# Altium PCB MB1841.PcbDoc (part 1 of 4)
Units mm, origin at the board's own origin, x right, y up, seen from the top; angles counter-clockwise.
Board outline 70 x 82.5 mm, 4 copper layers (Top Layer, Signal Layer 1, Signal Layer 2, Bottom Layer), stack 1.49 mm thick; 252 components, 169 nets, 1058 pads, 796 vias.
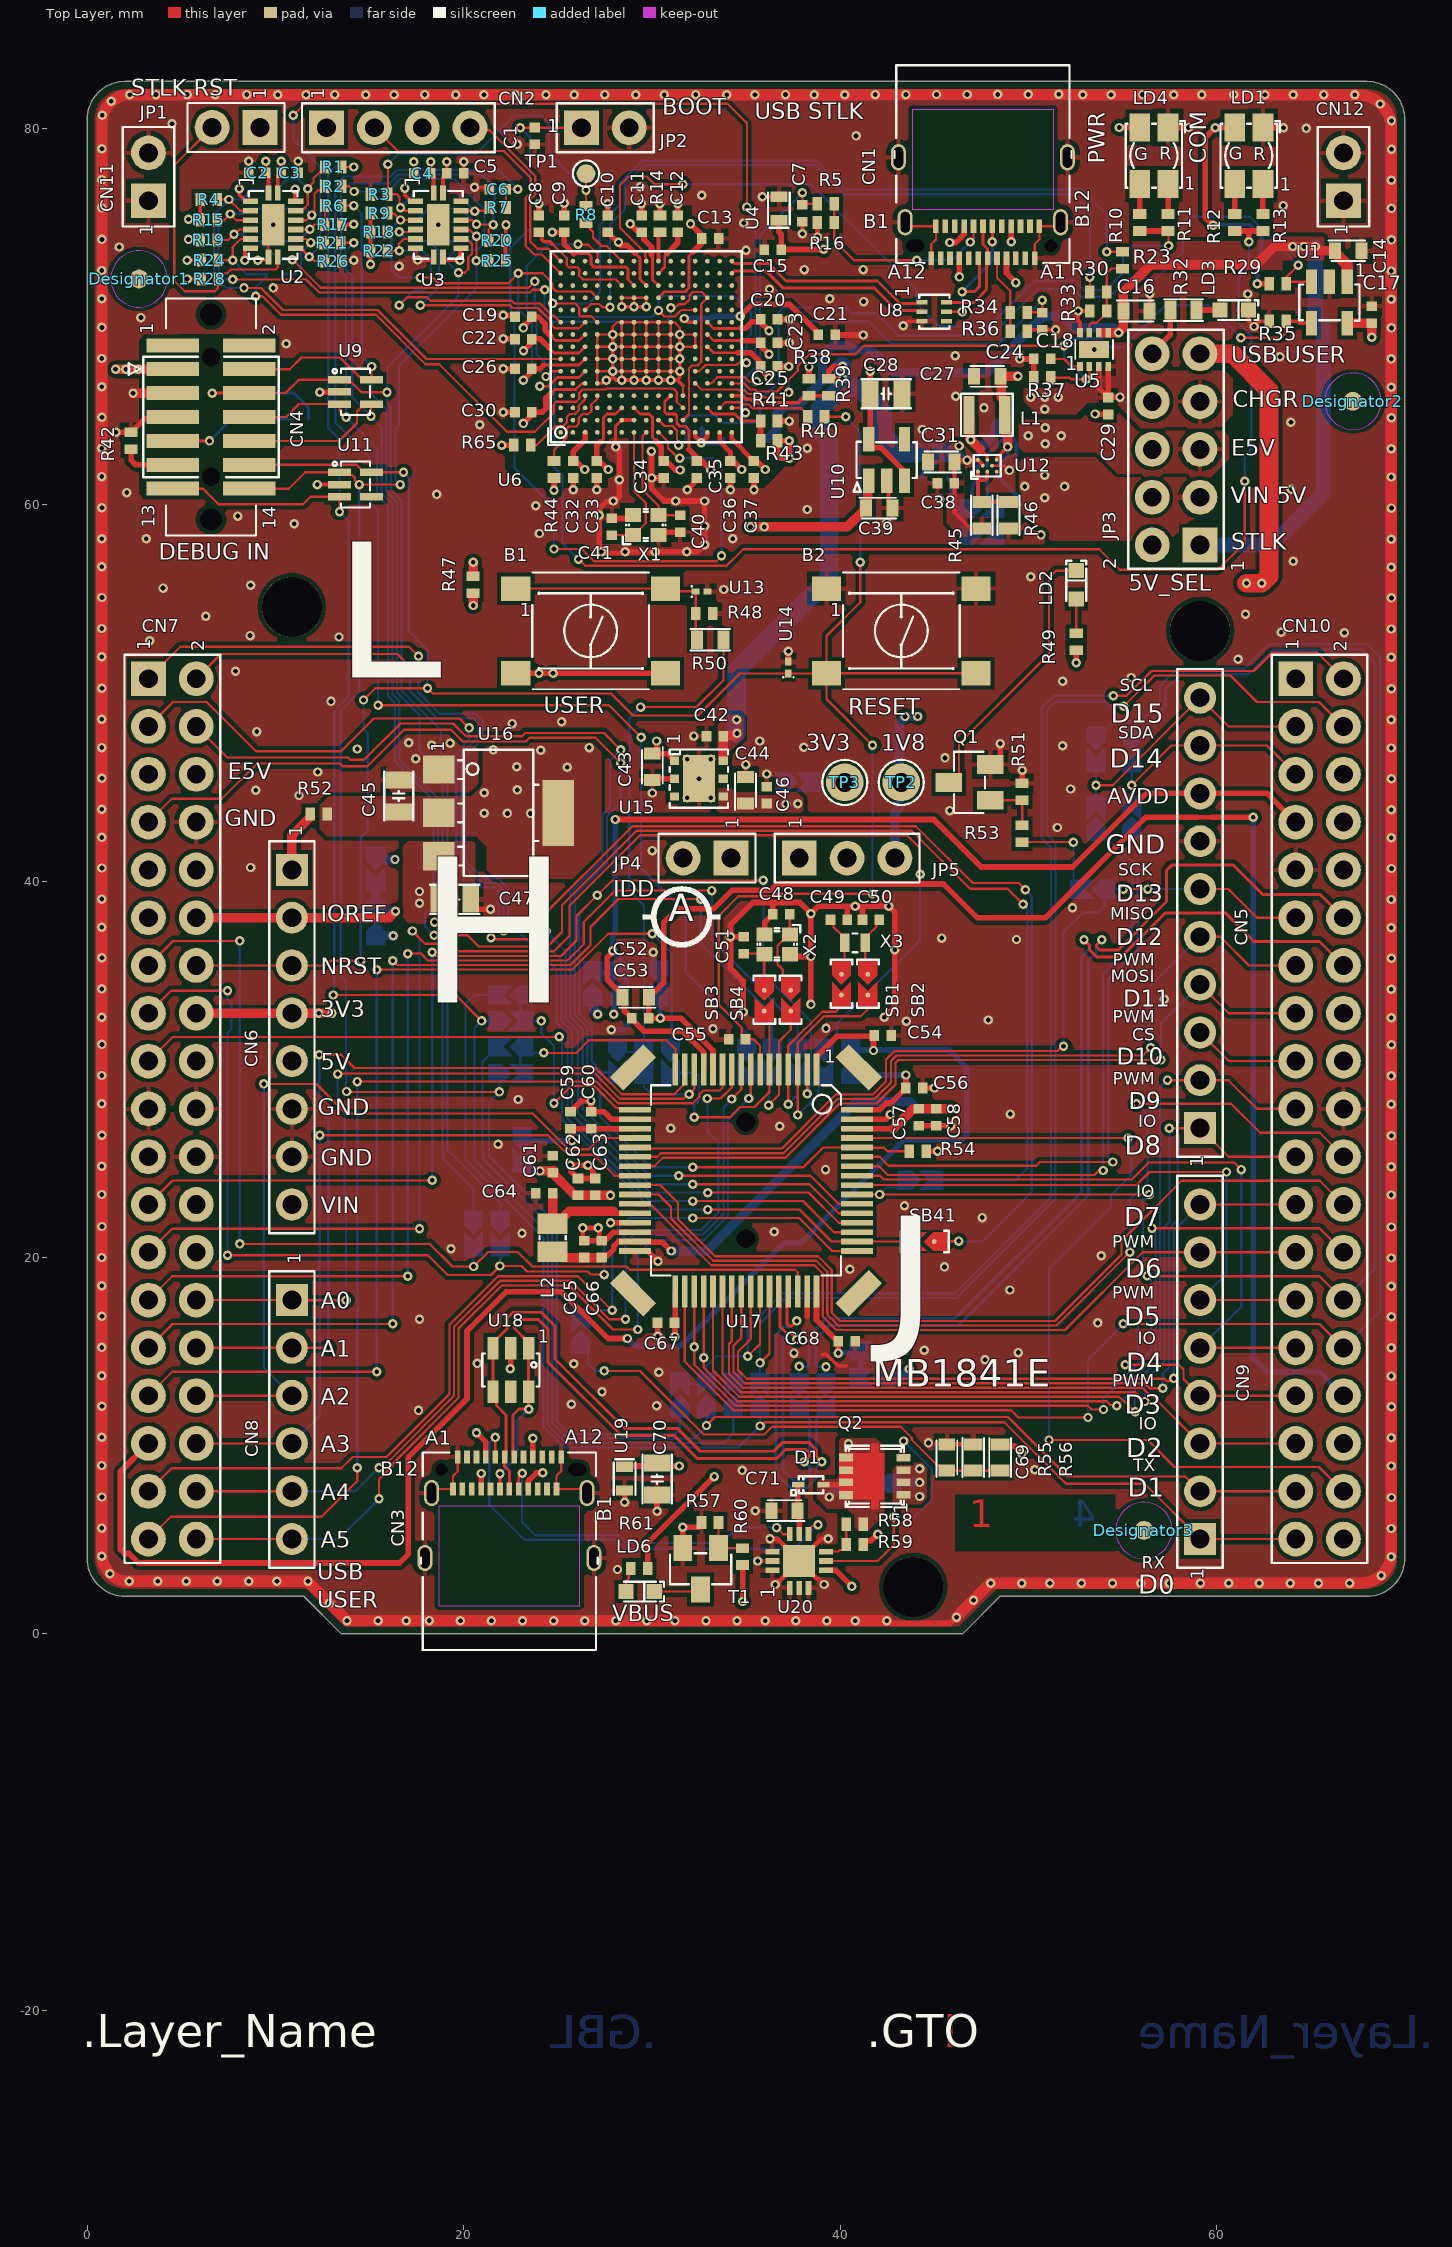
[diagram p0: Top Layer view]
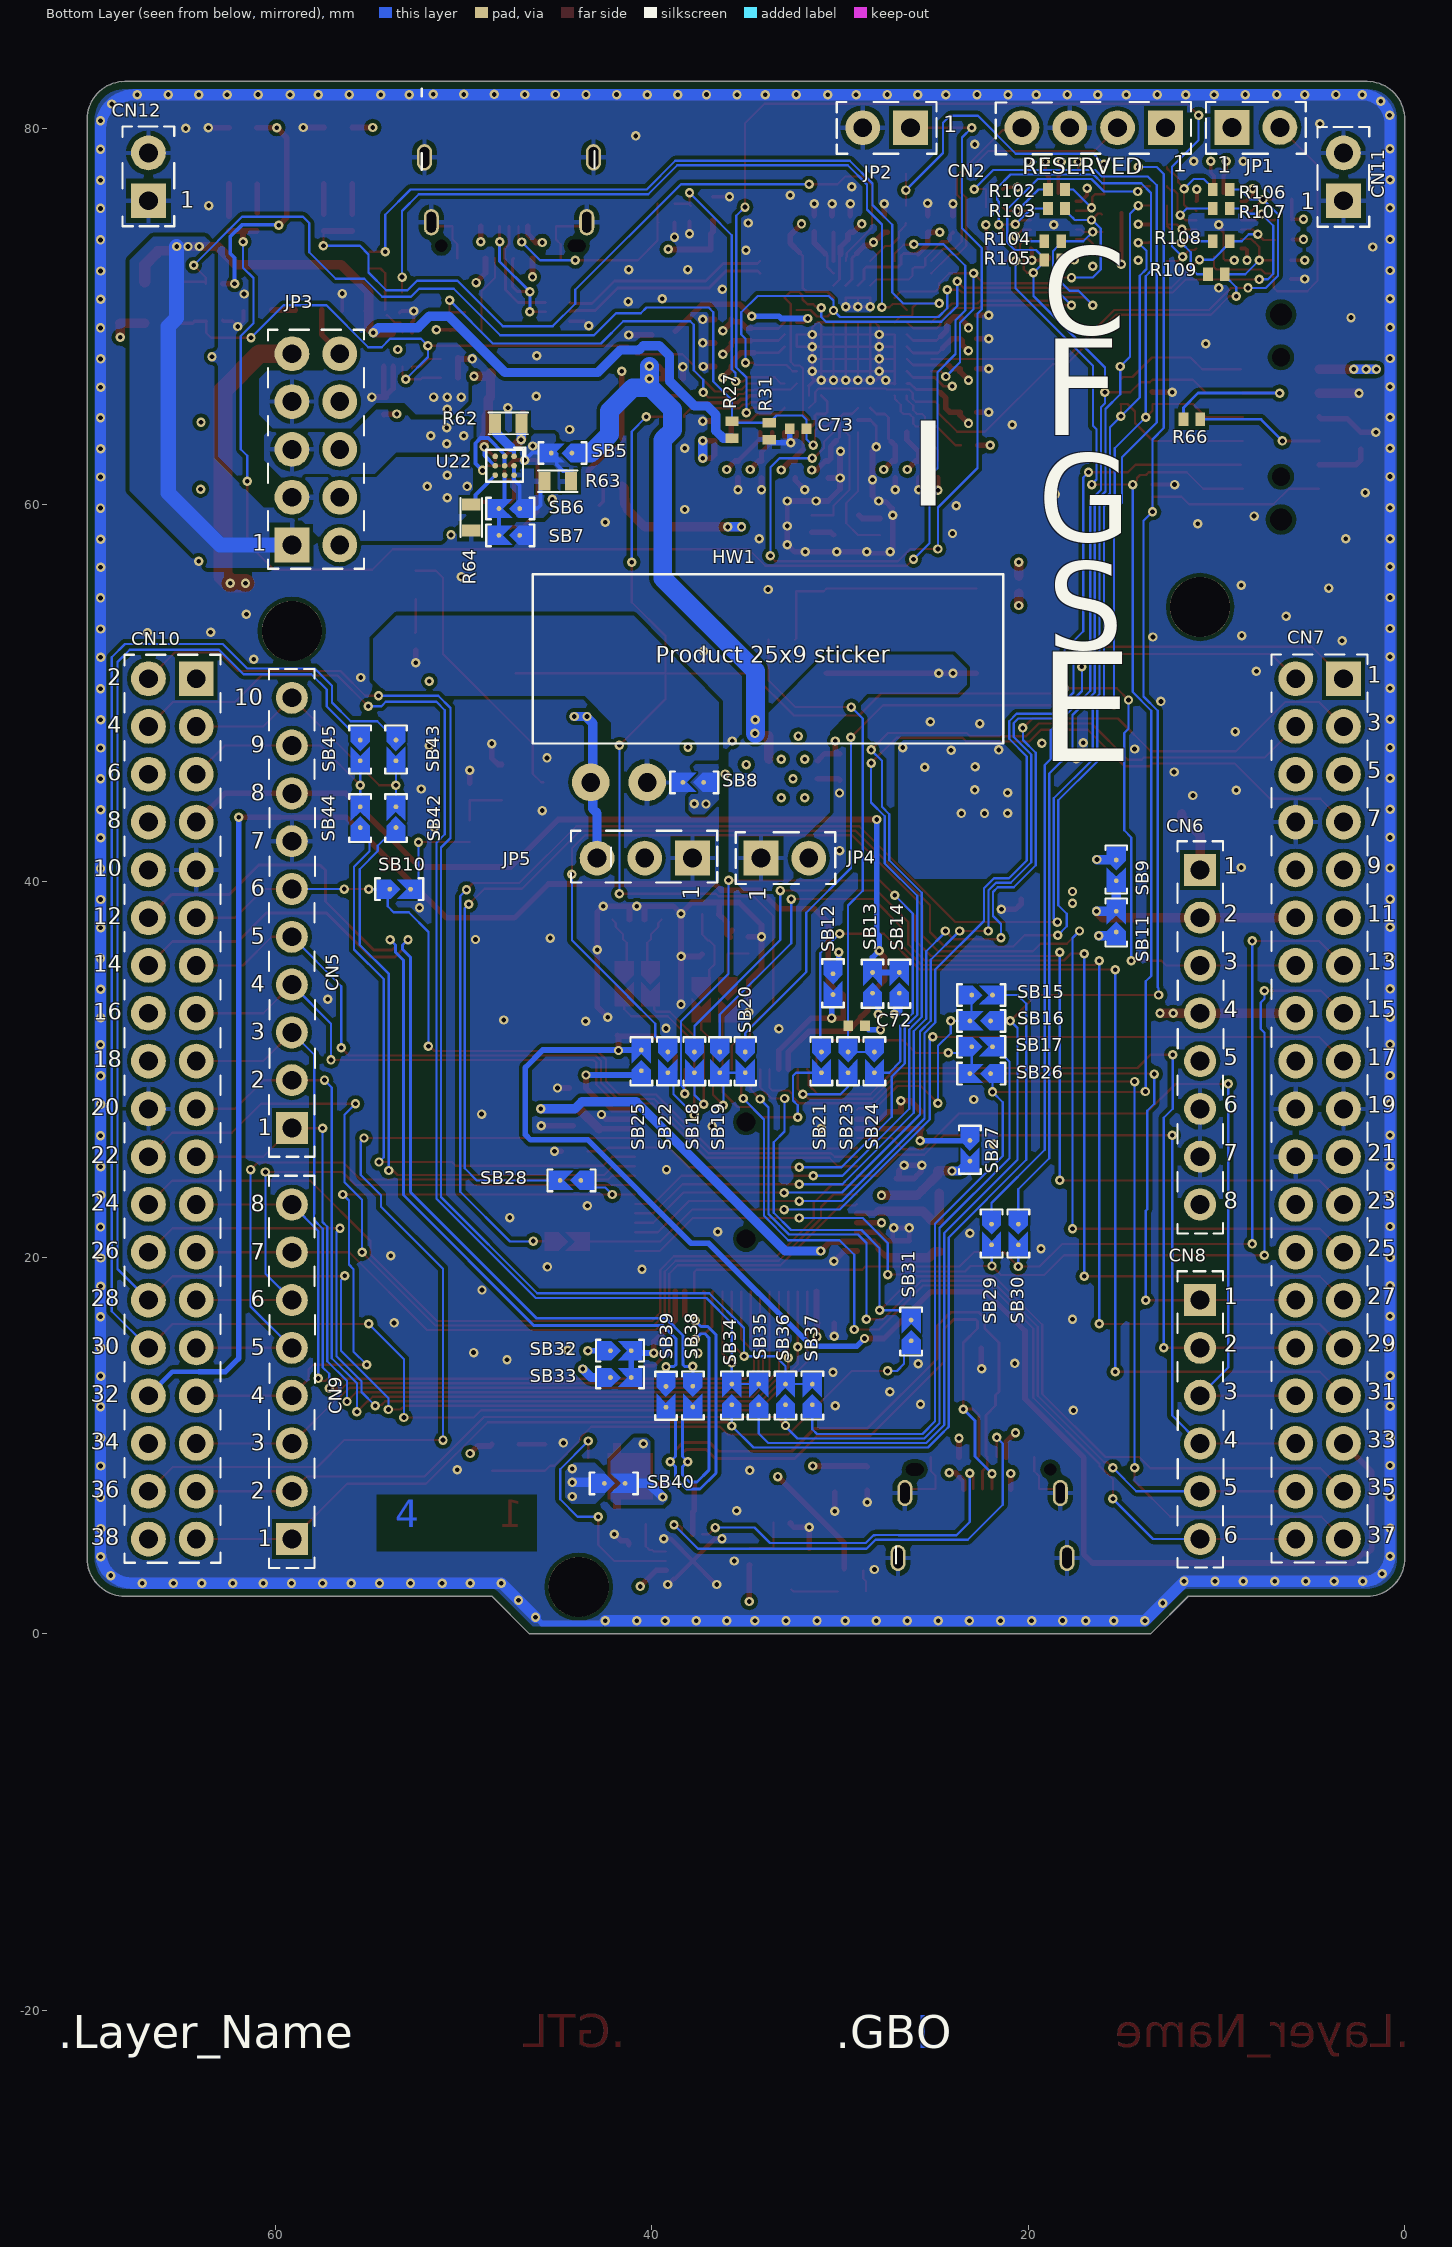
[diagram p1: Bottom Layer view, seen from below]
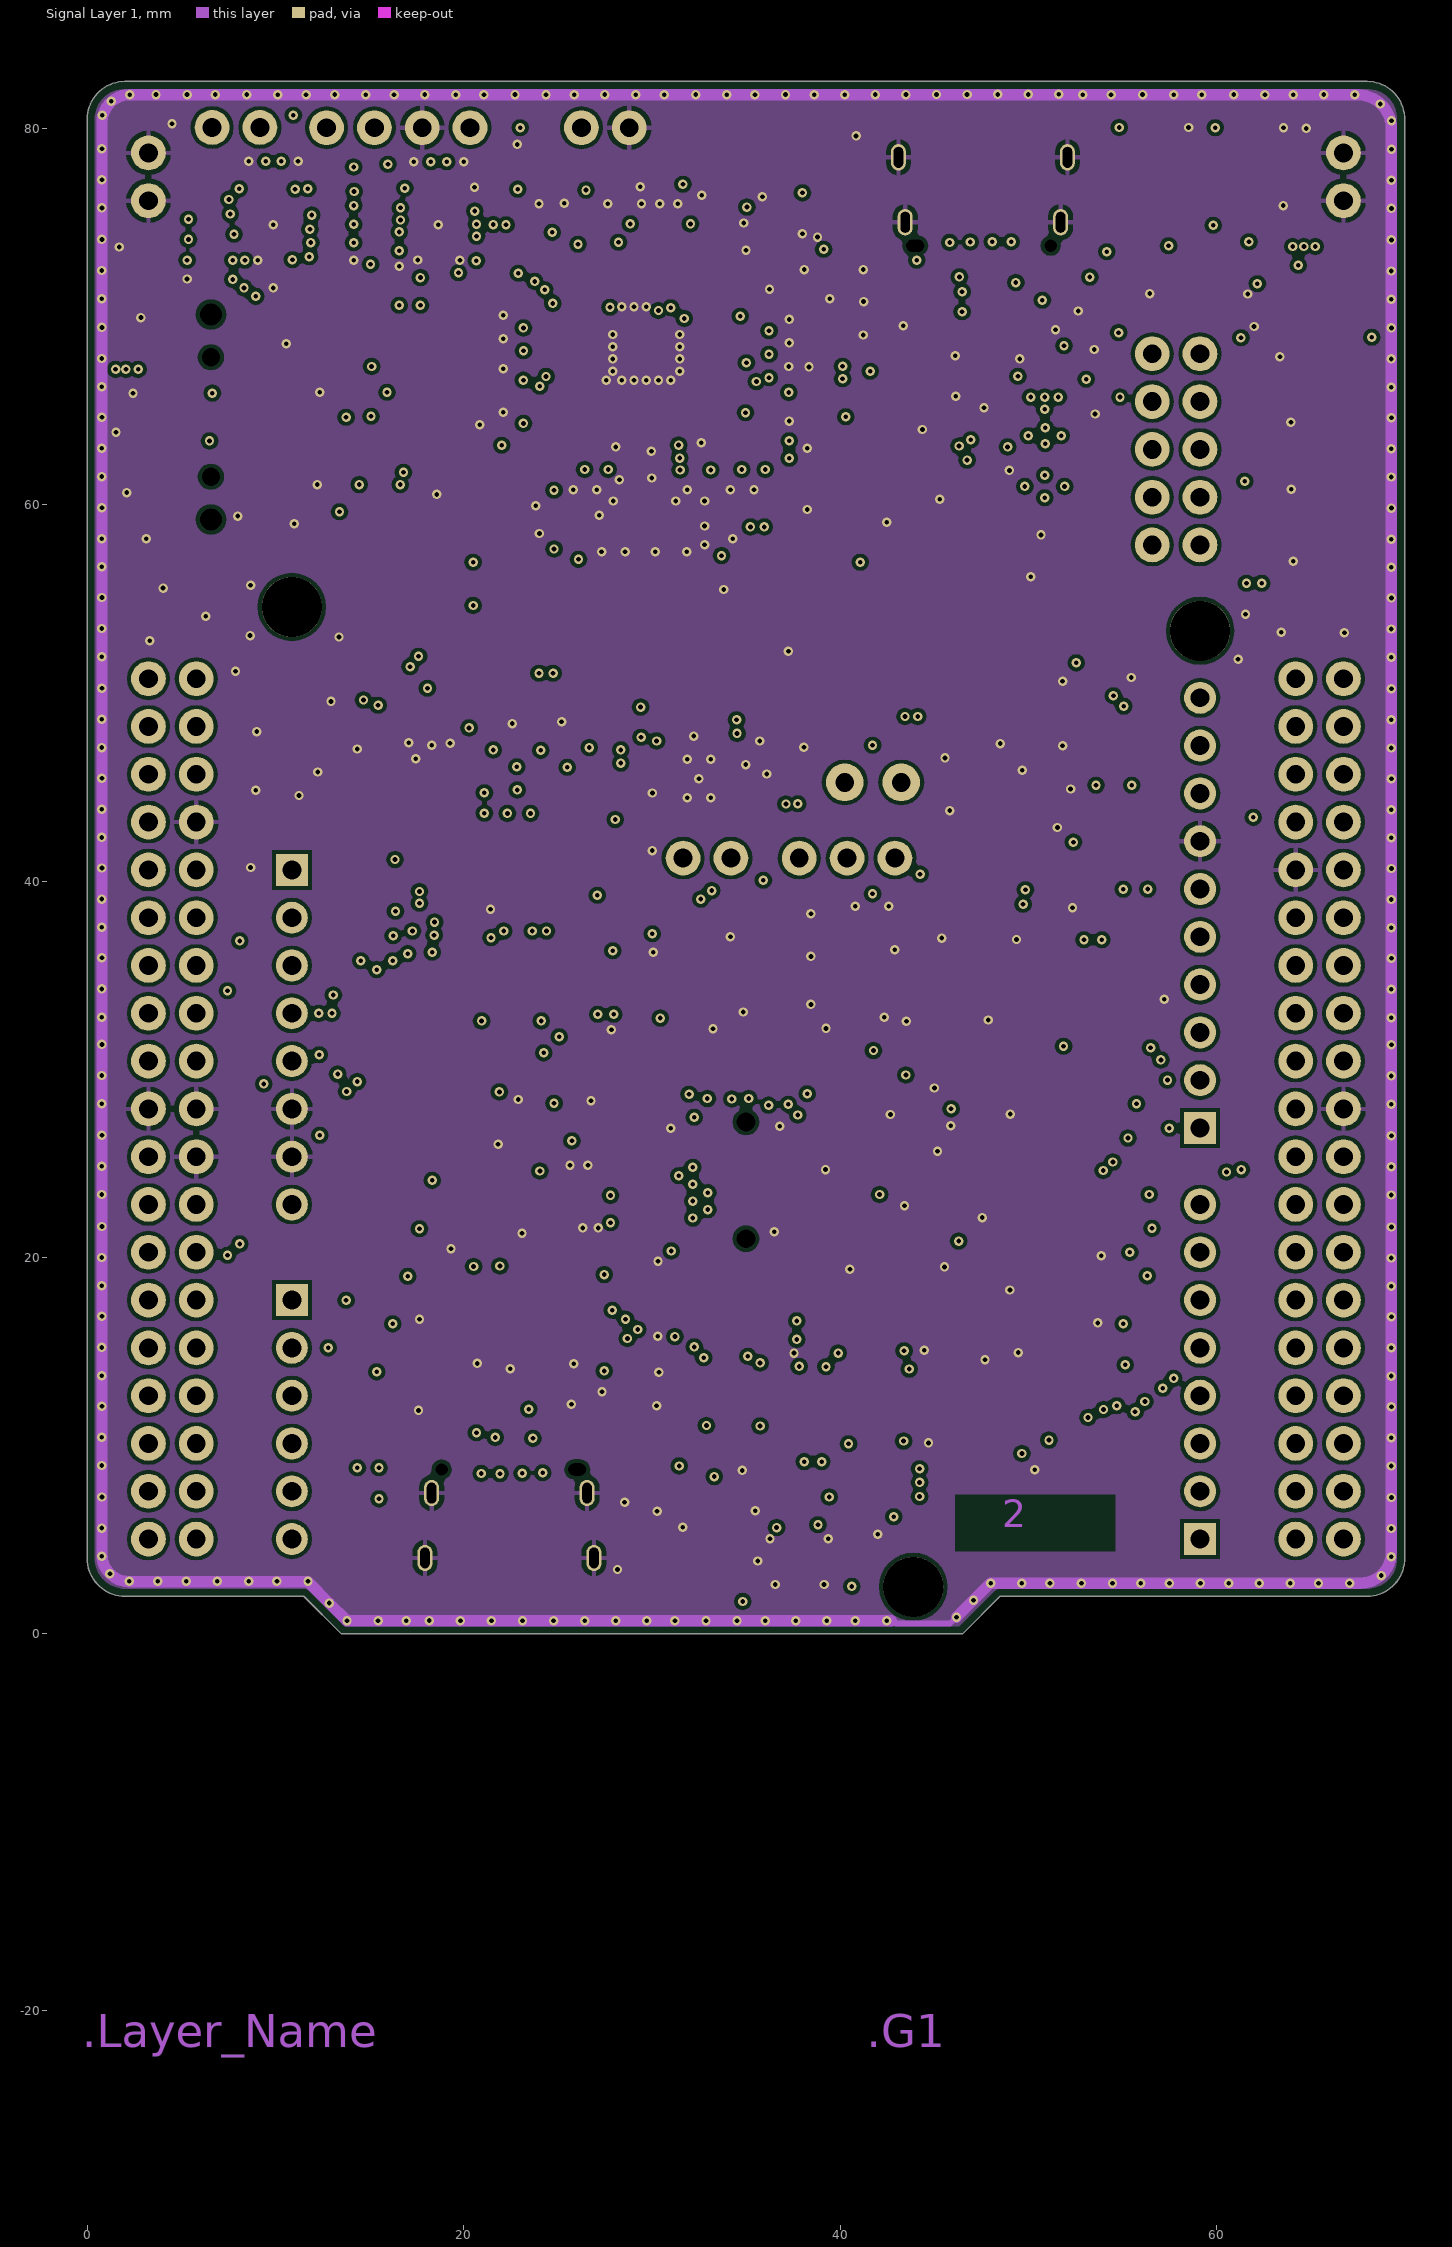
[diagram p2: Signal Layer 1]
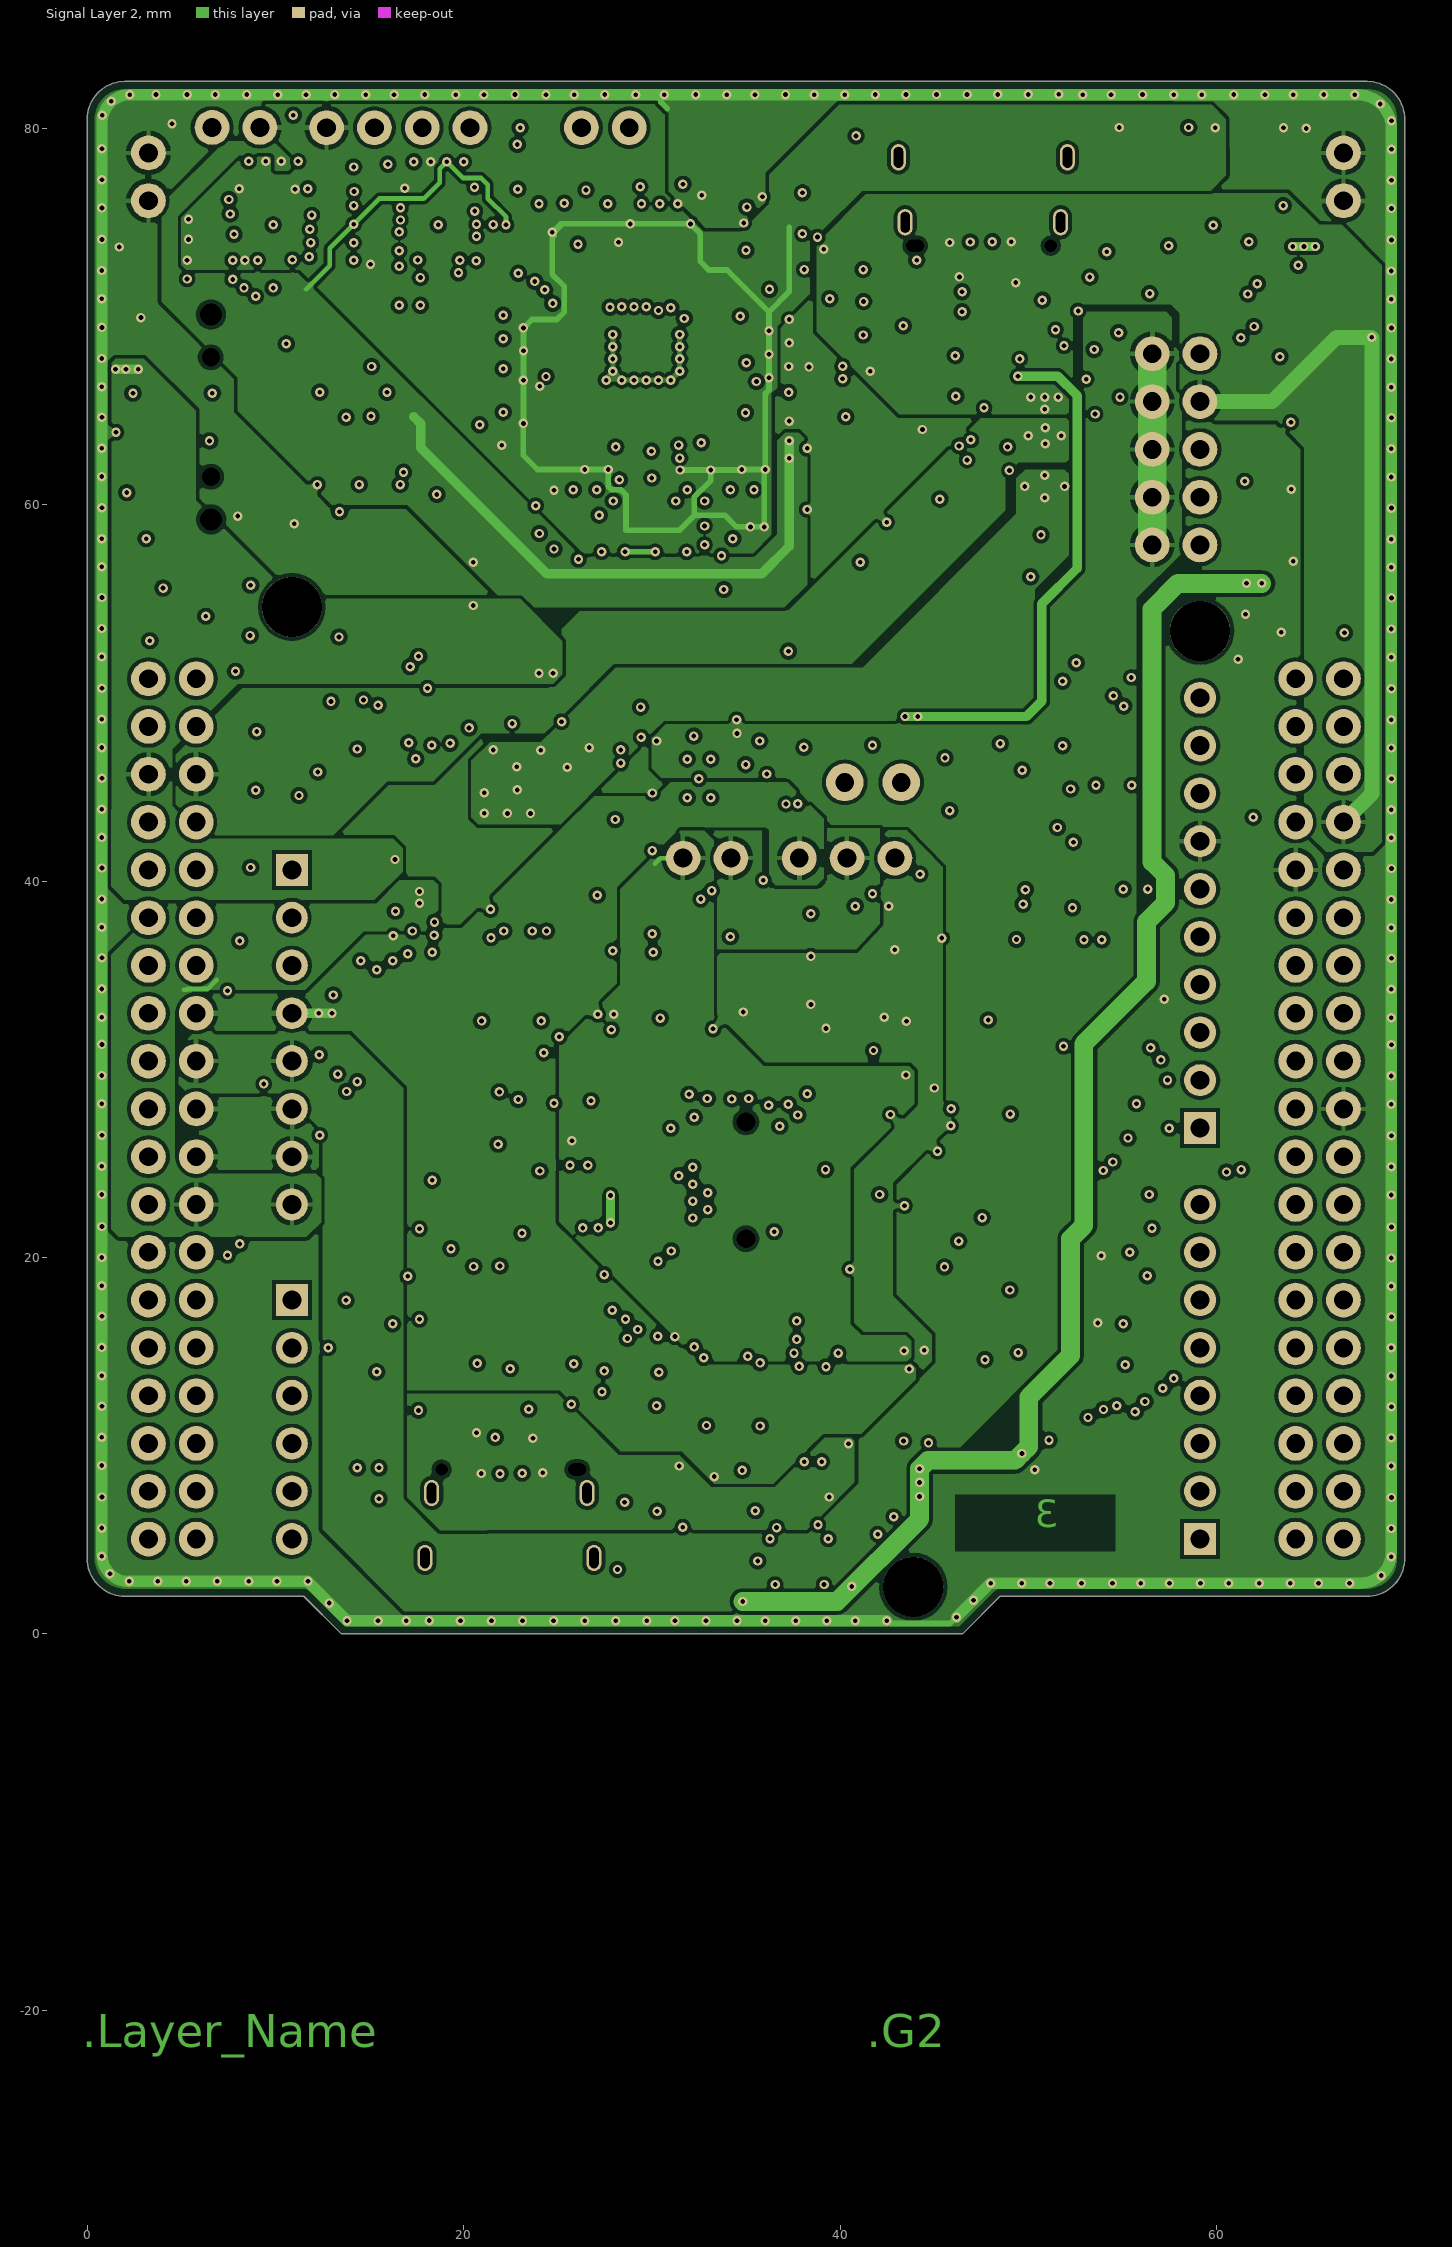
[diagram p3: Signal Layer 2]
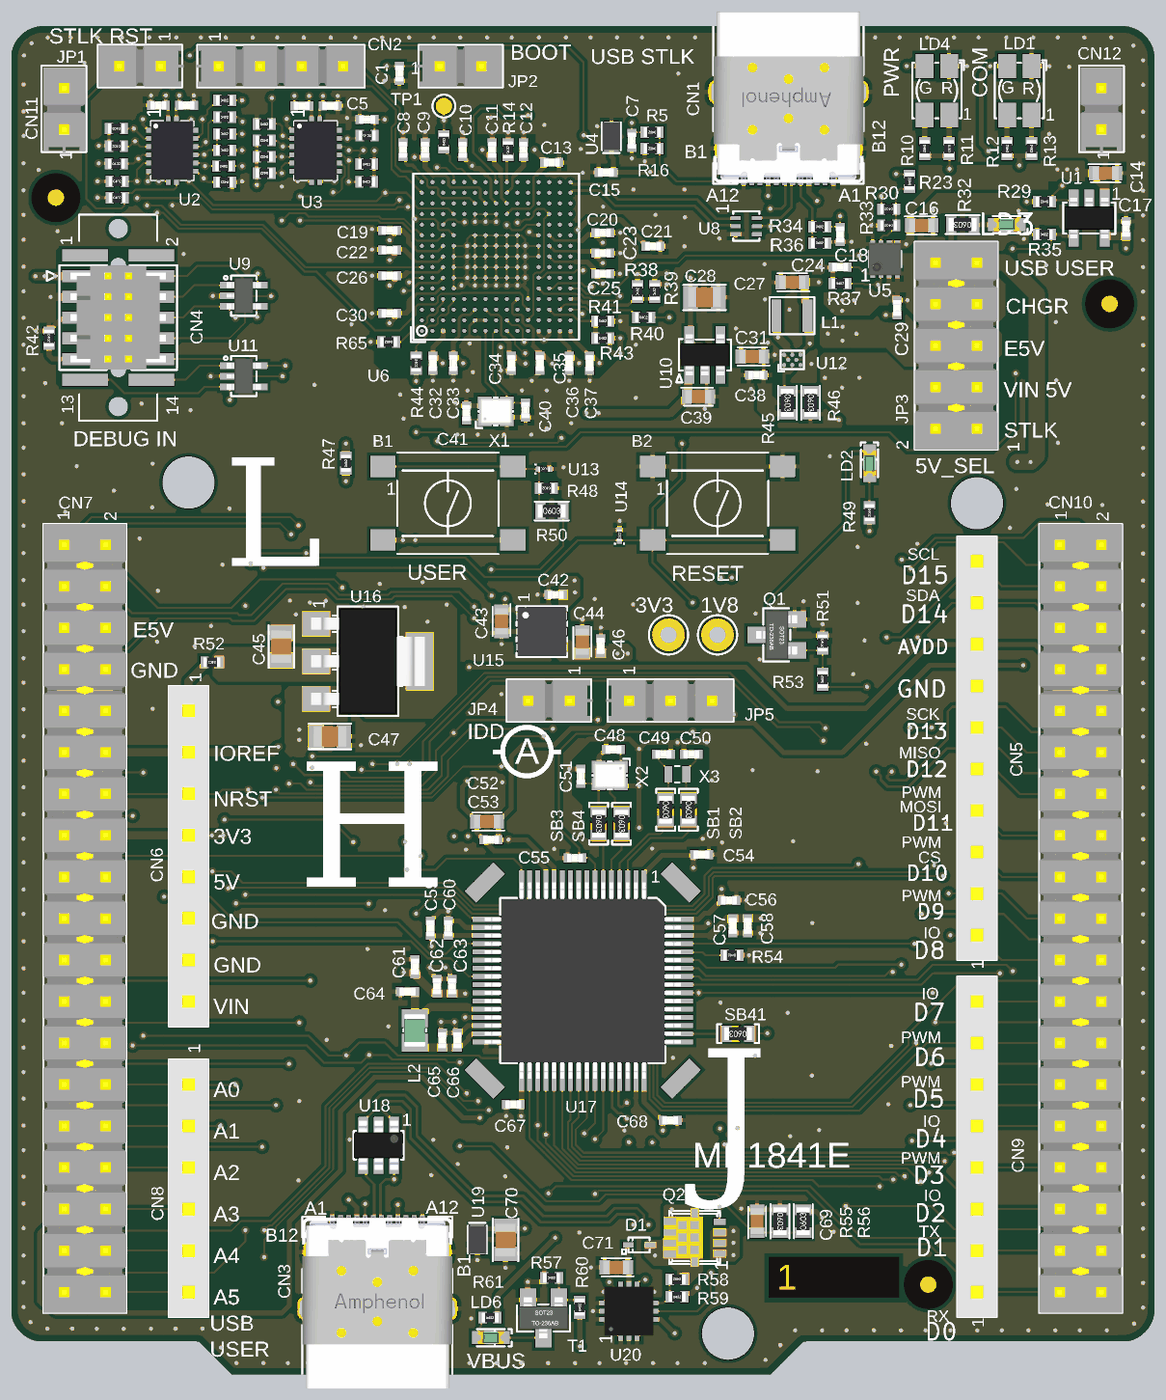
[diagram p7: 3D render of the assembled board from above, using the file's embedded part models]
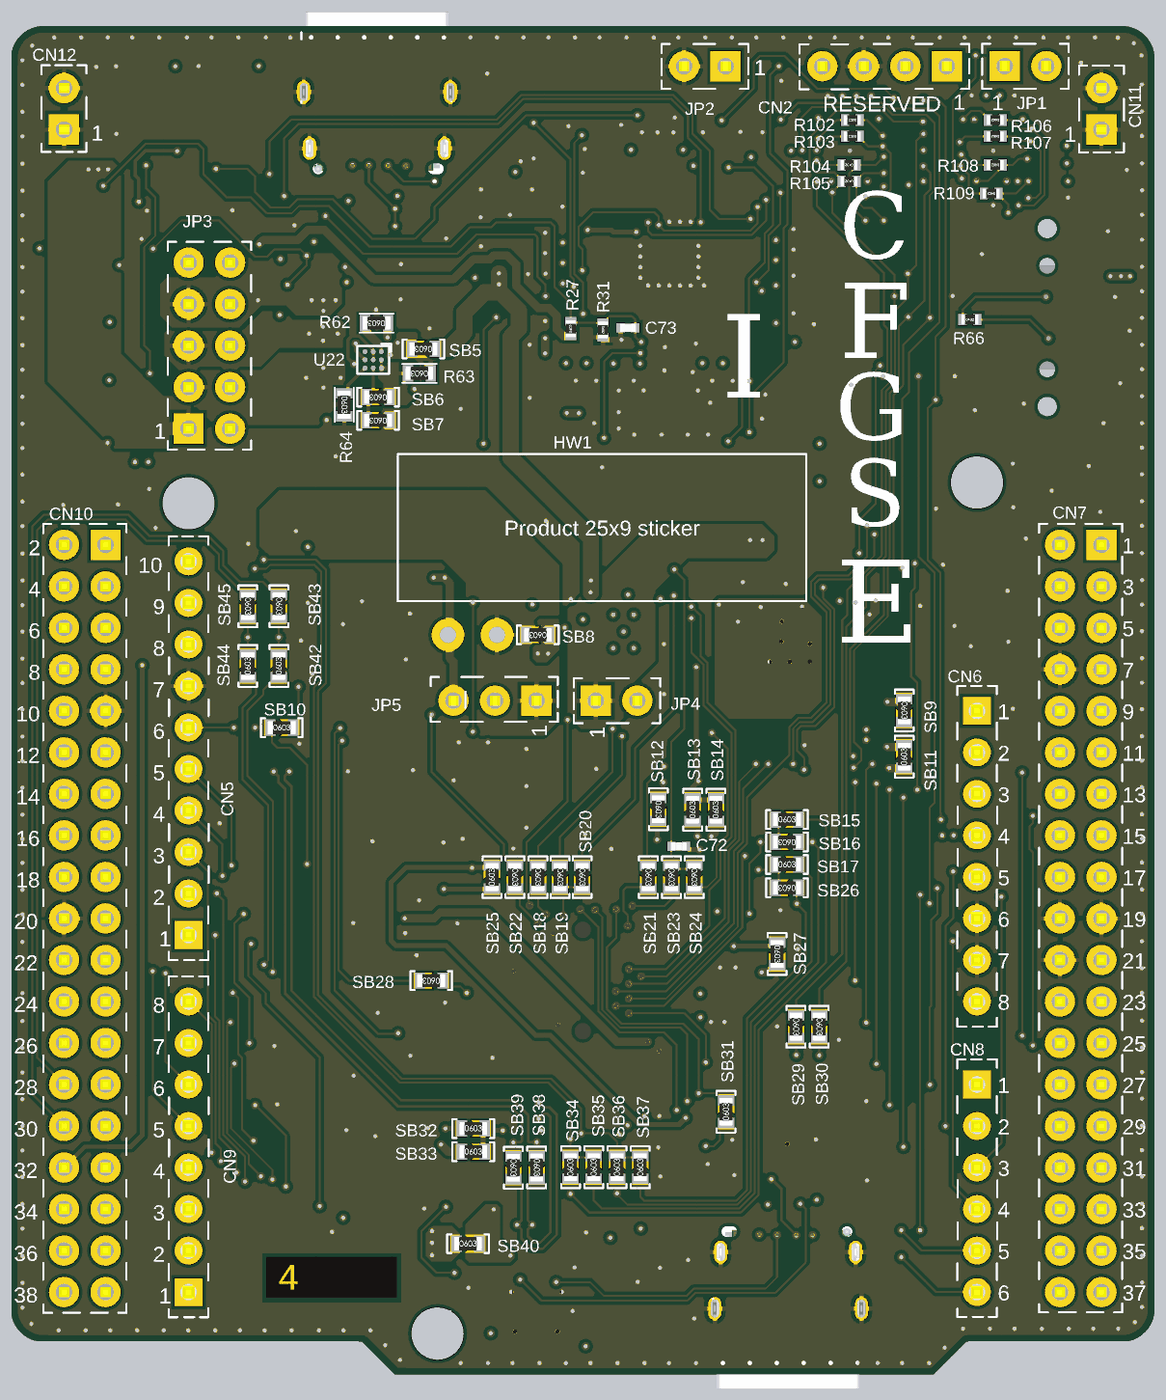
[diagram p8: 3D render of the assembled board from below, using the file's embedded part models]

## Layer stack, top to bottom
Top Solder: solder mask 0.015, Solder Resist, Dk 3.5
Top Layer: signal copper 0.035
Dielectric 1: prepreg 0.108, Dk 4.2
Signal Layer 1: signal copper 0.035
Dielectric 2: core 1.134, FR4, Dk 4.2
Signal Layer 2: signal copper 0.035
Dielectric 3: prepreg 0.108, Dk 4.2
Bottom Layer: signal copper 0.035
Bottom Solder: solder mask 0.015, Solder Resist, Dk 3.5

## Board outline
2,2 11.5,2 13.5,0 46.5,0 48.5,2 68,2 ccw(c68,4) 70,4 70,80.5 ccw(c68,80.5) 68,82.5 2,82.5 ccw(c2,80.5) 0,80.5 0,4 ccw(c2,4)

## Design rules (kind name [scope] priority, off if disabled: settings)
BoardOutlineClearance [All] p1: gap=0.4 ignorepadtopadclearanceinfootprint=FALSE
Clearance [All] p1: gap=0.12 ignorepadtopadclearanceinfootprint=FALSE except(0: Arc-Hole Track-Hole SMDPad-Hole THPad-Hole Via-Hole Fill-Hole Poly-Hole Region-Hole Text-Hole; 0.2: Arc-THPad Arc-Fill Arc-Poly Track-THPad Track-Fill Track-Poly SMDPad-SMDPad SMDPad-THPad SMDPad-Fill SMDPad-Poly THPad-THPad THPad-Fill THPad-Poly Via-Fill Via-Poly Fill-Fill Fill-Poly Poly-Poly)
ComponentClearance [All] p1 off: gap=0.025 collisioncheckmode=3 verticalgap=2540 showdistances=TRUE
DiffPairsRouting DiffPairsRouting_USB [InDifferentialPairClass('All Differential Pairs')] p1: maxlimit=0.226 minlimit=0.127 mostfreqgap=0.226 toplayer_mingap=0.226 toplayer_minwidth=0.155 toplayer_maxwidth=0.155 toplayer_prefwidth=0.155 midlayer1_minwidth=0.381 midlayer1_maxwidth=0.381 midlayer1_prefwidth=0.381 midlayer2_minwidth=0.381 midlayer2_maxwidth=0.381 midlayer2_prefwidth=0.381 bottomlayer_mingap=0.226 bottomlayer_minwidth=0.155 bottomlayer_maxwidth=0.155 bottomlayer_prefwidth=0.155 maxuncoupledlength=50
FanoutControl Fanout_BGA [IsBGA] p1: bgadir=Out bgaviamode=Closest fanoutstyle=Auto fanoutdirection=Alternating viagrid=0.025 // Fanout_BGA (Default Rule)
FanoutControl Fanout_LCC [IsLCC] p2: bgadir=Out bgaviamode=Closest fanoutstyle=Auto fanoutdirection=Alternating viagrid=0.025 // Fanout_LCC (Default Rule)
FanoutControl Fanout_SOIC [IsSOIC] p3: bgadir=Out bgaviamode=Closest fanoutstyle=Auto fanoutdirection=Alternating viagrid=0.025 // Fanout_SOIC (Default Rule)
FanoutControl Fanout_Small [(CompPinCount < 5)] p4: bgadir=Out bgaviamode=Closest fanoutstyle=Auto fanoutdirection=OutThenIn viagrid=0.025 // Fanout_Small (Default Rule)
FanoutControl Fanout_Default [All] p5: bgadir=Out bgaviamode=Closest fanoutstyle=Auto fanoutdirection=Alternating viagrid=0.025 // Fanout_Default (Default Rule)
Height [All] p1 off: minheight=0 maxheight=100 prefheight=0.5
HoleSize [All] p1: absolutevalues=TRUE maxlimit=10 minlimit=0.15 maxpercent=80.000 minpercent=20.000
HoleToHoleClearance [All] p1: gap=0.25 allowstackedmicrovias=TRUE
Length Length_USB [InNetClass('USB')] p1: maxlimit=50 minlimit=1
MatchedLengths "Schematic Matched Net Lengths_5" [InNet('USB_DEV_HS_N')] p1: tolerance=0.2 checknetsindiffpair=TRUE checkdiffpairvsdiffpair=FALSE checkxsignals=FALSE checkothers=FALSE
MatchedLengths "Schematic Matched Net Lengths_4" [InNet('USB_DEV_HS_P')] p2: tolerance=0.2 checknetsindiffpair=TRUE checkdiffpairvsdiffpair=FALSE checkxsignals=FALSE checkothers=FALSE
MatchedLengths [InDifferentialPairClass('DIFF_USB')] p3: tolerance=0.2 checknetsindiffpair=TRUE checkdiffpairvsdiffpair=FALSE checkxsignals=FALSE checkothers=FALSE
MaxMinImpedance "Schematic Impedance Constraint_3" [InNet('STLK_USB_P')] p1: minimum=85.00 maximum=95.00
MaxMinImpedance "Schematic Impedance Constraint_2" [InNet('STLK_USB_N')] p2: minimum=85.00 maximum=95.00
MaxMinImpedance "Schematic Impedance Constraint_1" [InNet('STLK_USB_CN_P')] p3: minimum=85.00 maximum=95.00
MaxMinImpedance "Schematic Impedance Constraint" [InNet('STLK_USB_CN_N')] p4: minimum=85.00 maximum=95.00
MaxMinImpedance "Schematic Impedance Constraint_5" [InNet('USB_DEV_HS_P')] p5: minimum=85.00 maximum=95.00
MaxMinImpedance "Schematic Impedance Constraint_4" [InNet('USB_DEV_HS_N')] p6: minimum=85.00 maximum=95.00
MinimumSolderMaskSliver [All] p1: minsoldermaskwidth=0.1
PlaneClearance [All] p1: clearance=0.6
PolygonConnect PolygonConnect_NO_FT [IsNamedPolygon('NO_FT')] p1: thpad.connectstyle=Relief thpad.reliefconductorwidth=0.25 thpad.reliefentries=4 thpad.polygonreliefangle="90 Angle" thpad.airgapwidth=0.25 smdpad.connectstyle=Direct smdpad.reliefconductorwidth=0.254 smdpad.reliefentries=4 smdpad.polygonreliefangle="90 Angle" smdpad.airgapwidth=0.254 via.connectstyle=Direct via.reliefconductorwidth=0.254 via.reliefentries=4 via.polygonreliefangle="90 Angle" via.airgapwidth=0.254
PolygonConnect PolygonConnect_6 [All vs IsNamedPolygon('GND_L01_P086')] p2: connectstyle=Relief reliefconductorwidth=0.254 reliefentries=4 polygonreliefangle="45 Angle" airgapwidth=0.254
PolygonConnect PolygonConnect_5 [All vs IsNamedPolygon('GND_L01_P084')] p3: connectstyle=Relief reliefconductorwidth=0.254 reliefentries=4 polygonreliefangle="45 Angle" airgapwidth=0.254
PolygonConnect PolygonConnect_4 [All vs IsNamedPolygon('GND_L01_P082')] p4: connectstyle=Relief reliefconductorwidth=0.254 reliefentries=4 polygonreliefangle="45 Angle" airgapwidth=0.254
PolygonConnect PolygonConnect_3 [All vs IsNamedPolygon('GND_L01_P010')] p5: connectstyle=Relief reliefconductorwidth=0.254 reliefentries=4 polygonreliefangle="45 Angle" airgapwidth=0.254
PolygonConnect PolygonConnect_2 [All vs IsNamedPolygon('NO_FT')] p6: connectstyle=Relief reliefconductorwidth=0.254 reliefentries=4 polygonreliefangle="45 Angle" airgapwidth=0.254
PolygonConnect PolygonConnect_1 [All vs IsNamedPolygon('NO_FT')] p7: connectstyle=Relief reliefconductorwidth=0.254 reliefentries=4 polygonreliefangle="45 Angle" airgapwidth=0.254
PolygonConnect [All vs IsNamedPolygon('NO_FT')] p8: connectstyle=Relief reliefconductorwidth=0.254 reliefentries=4 polygonreliefangle="45 Angle" airgapwidth=0.254
PolygonConnect PolygonConnect__DEFAULT [All] p9: thpad.connectstyle=Relief thpad.reliefconductorwidth=0.25 thpad.reliefentries=4 thpad.polygonreliefangle="90 Angle" thpad.airgapwidth=0.25 smdpad.connectstyle=Relief smdpad.reliefconductorwidth=0.25 smdpad.reliefentries=4 smdpad.polygonreliefangle="90 Angle" smdpad.airgapwidth=0.25 via.connectstyle=Direct via.reliefconductorwidth=0.254 via.reliefentries=4 via.polygonreliefangle="45 Angle" via.airgapwidth=0.254
RoutingVias [All] p1: holewidth=0.25 width=0.5 viastyle="Through Hole" minholewidth=0.25 minwidth=0.5 maxholewidth=0.25 maxwidth=0.5
SilkToSilkClearance [All] p1: silktosilkclearance=0
SilkToSolderMaskClearance [IsPad] p1: minsilkscreentomaskgap=0 clearancetoexposedcopper=TRUE
SolderMaskExpansion [All] p1: expansion=0.05 istentingtop=FALSE
Width Width_ALIM [InNetClass('ALIM')] p1: maxlimit=10 minlimit=0.12 preferedwidth=0.3
Width [All] p2: maxlimit=10 minlimit=0.12 preferedwidth=0.12
16 further rules are at their usual default settings.

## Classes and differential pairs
net class PC[0..15]: PC0 PC1 PC2 PC3 PC6 PC7 PC8 PC9 PC10 PC11 PC12 PC13 PC14 PC15
net class PB[0..15]: PB0 PB1 PB2 PB3 PB4 PB5 PB6 PB7 PB8 PB10 PB13 PB14 PB15
net class PA[0..15]: PA0 PA1 PA2 PA3 PA4 PA5 PA6 PA7 PA8 PA9 PA10 PA11 PA12 PA13 PA14 PA15
component class U_USB: C69 C70 C71 CN3 D1 LD6 Q2 R55 R56 R57 R58 R59 R60 R61 SB40 T1 U18 U19 U20
component class U_STM32_microcontroller_power: C52 C53 C54 C56 C57 C58 C59 C60 C61 C62 C63 C64 C65 C66 C67 C68 HW2 JP4 L2 SB12 SB13 SB14 SB25 SB27 SB32 SB33
component class U_STM32_microcontroller_IOs: B1 B2 C48 C49 C50 C51 C55 C72 HW17 HW18 HW110 R48 R50 R54 SB1 SB2 SB3 SB4 SB15 SB16 SB17 SB18 SB19 SB20 SB21 SB22 SB23 SB24 SB26 SB28 SB29 SB30 SB31 SB34 SB35 SB36 SB37 SB38 SB39 SB41 U13 U14 U17 X2 X3
component class U_STLink_V3EC: C1 C2 C3 C4 C5 C6 C7 C8 C9 C10 C11 C12 C13 C14 C15 C16 C17 C18 C19 C20 C21 C22 C23 C24 C25 C26 C28 C29 C30 C32 C33 C34 C35 C36 C37 C39 C40 C41 C73 CN1 CN2 HW1 HW3 HW4 HW12 JP1 JP2 LD1 LD4 R1 R2 R3 R4 R5 R6 R7 R8 R9 R10 R11 R12 R13 R14 R15 R16 R17 R18 R19 R20 R21 R22 R23 R24 R25 R26 R27 R28 R29 R30 R31 R33 R34 R35 R36 R37 R38 R39 R40 R41 R43 R44 R47 R65 R102 R103 R104 R105 R106 R107 R108 R109 TP1 U1 U2 U3 U4 U5 U6 U8 U10 X1
component class U_Power: C27 C31 C38 C42 C43 C44 C45 C46 C47 CN11 CN12 HW5 HW6 JP3 JP5 L1 LD3 R32 R45 R46 R62 R63 R64 SB5 SB6 SB7 SB8 TP2 TP3 U12 U15 U16 U22
component class U_Arduino_extension_connectors: CN5 CN6 CN7 CN8 CN9 CN10 LD2 Q1 R49 R51 R52 R53 SB9 SB10 SB11 SB42 SB43 SB44 SB45
net class PH[0..1]: PH0 PH1
component class U_External_Debug_Interface: CN4 R42 R66 U9 U11
component class Project_overview: HW1 HW7
differential pair USB_FS: +USB_FS_P -USB_FS_N
differential pair STLK_USB_CN: +STLK_USB_CN_P -STLK_USB_CN_N
differential pair STLK_USB: +STLK_USB_P -STLK_USB_N

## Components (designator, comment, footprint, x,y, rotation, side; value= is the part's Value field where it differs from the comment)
B1 "SW_PUSH_SMD" SWI_APEM_ADTSM644SV_BLUE 26.745,53.3 r0 top locked value=SW-PUSH-ADTSM644KV
B2 "SW_PUSH_SMD" SWI_APEM_ADTSM644KV_BLACK 43.255,53.3 r0 top locked value=SW-PUSH-ADTSM644KV
C1 "Capacitor" C0402 23.775,79.6 r90 top value=100nF
C2 "Capacitor" C0402 9.025,77.65 r0 top value=100nF
C3 "Capacitor" C0402 10.75,77.65 r0 top value=100nF
C4 "Capacitor" C0402 17.8,77.625 r0 top value=100nF
C5 "Capacitor" C0402 19.55,77.625 r180 top value=100nF
C6 "Capacitor" C0402 21.8,76.775 r180 top value=20pF
C7 "Capacitor" C0402 37.997,75.5 r270 top value=10nF
C8 "Capacitor" C0402 24,74.925 r270 top value=2.2uF
C9 "Capacitor" C0402 25.35,74.925 r90 top value=100nF
C10 "Capacitor" C0402 27.65,74.925 r90 top value=100nF
C11 "Capacitor" C0402 29.45,74.925 r90 top value=100nF
C12 "Capacitor" C0402 31.375,74.925 r270 top value=2.2uF
C13 "Capacitor" C0402 33.1,74.15 r0 top value=100nF
C14 "Capacitor" C0603 67,73.5 r180 top value=10uF
C15 "Capacitor" C0402 36.425,73.55 r180 top value=100pF
C16 "Capacitor" C0603 55.75,70.3 r180 top value=10uF
C17 "Capacitor" C0402 68.25,70.1 r270 top value=100nF
C18 "Capacitor" C0402 50.75,69.75 r270 top value=10nF
C19 "Capacitor" C0402 23.175,70 r180 top value=100nF
C20 "Capacitor" C0402 36.225,69.85 r0 top value=100nF
C21 "Capacitor" C0402 39.3,69.025 r180 top value=2.2uF
C22 "Capacitor" C0402 23.175,68.8 r180 top value=100nF
C23 "Capacitor" C0402 36.225,68.6 r0 top value=100nF
C24 "Capacitor" C0402 50.75,67.75 r0 top value=10nF
C25 "Capacitor" C0402 36.225,67.35 r0 top value=100nF
C26 "Capacitor" C0402 23.175,67.225 r180 top value=100nF
C27 "Capacitor" C0603 47.825,66.825 r0 top value=10uF
C28 "Capacitor" C0805 42.45,65.9 r180 top value=2.2uF
C29 "Capacitor" C0402 54.25,65.25 r90 top value=100nF
C30 "Capacitor" C0402 23.175,64.925 r180 top value=100nF
C31 "Capacitor" C0603 45.375,62.275 r0 top value=10uF
C32 "Capacitor" C0402 25.825,61.875 r270 top value=100nF
C33 "Capacitor" C0402 27.075,61.875 r270 top value=100nF
C34 "Capacitor" C0402 30.625,61.875 r270 top value=100nF
C35 "Capacitor" C0402 32.375,61.875 r270 top value=100nF
C36 "Capacitor" C0402 34.175,61.875 r270 top value=100nF
C37 "Capacitor" C0402 35.425,61.875 r270 top value=100nF
C38 "Capacitor" C0402 45.625,61.15 r0 top value=100nF
C39 "Capacitor" C0603 42.075,59.825 r180 top value=10uF
C40 "Capacitor" C0402 31.5,59 r270 top value=5.6pF
C41 "Capacitor" C0402 27.875,58.825 r90 top value=5.6pF
C42 "Capacitor" C0402 33.35,47.7 r0 top value=100nF
C43 "Capacitor" C0603 30.025,46.075 r90 top value=1uF
C44 "Capacitor" C0603 34.975,44.825 r270 top value=1uF
C45 "Capacitor" C0805 16.55,44.53 r270 top value=10uF
C46 "Capacitor" C0402 36.1,44.575 r270 top value=100nF
C47 "Capacitor" C0805 19.525,39.03 r180 top value=10uF
C48 "Capacitor" C0402 36.881,38.244 r0 top value=6.8pF
C49 "Capacitor" C0402 39.94,37.95 r180 top value=6.8pF
C50 "Capacitor" C0402 41.64,37.95 r0 top value=6.8pF
C51 "Capacitor" C0402 34.875,36.6 r270 top value=6.8pF
C52 "Capacitor" C0603 29.14,33.825 r0 top value=1uF
C53 "Capacitor" C0402 29.385,32.715 r180 top value=100nF
C54 "Capacitor" C0402 42.275,31.8 r180 top value=100nF
C55 "Capacitor" C0402 34.525,31.6 r0 top value=100nF
C56 "Capacitor" C0402 43.943,29.01 r180 top value=100nF
C57 "Capacitor" C0402 44.175,27.45 r90 top value=100nF
C58 "Capacitor" C0402 45.1,27.45 r90 top value=2.2uF
C59 "Capacitor" C0402 25.675,27.3 r270 top value=10uF
C60 "Capacitor" C0402 26.775,27.3 r270 top value=100nF
C61 "Capacitor" C0402 24.725,24.95 r270 top value=10uF
C62 "Capacitor" C0402 26.075,23.75 r270 top value=10uF
C63 "Capacitor" C0402 27,23.75 r270 top value=100nF
C64 "Capacitor" C0402 24.275,23.425 r0 top value=100pF
C65 "Capacitor" C0402 26.4,20.45 r270 top value=2.2uF
C66 "Capacitor" C0402 27.325,20.45 r270 top value=100nF
C67 "Capacitor" C0402 30.75,16.525 r0 top value=100nF
C68 "Capacitor" C0402 40.35,15.55 r180 top value=100nF
C69 "Capacitor" C0603 45.675,9.375 r270 top value=10pF
C70 "Capacitor" C0805 30.275,8.225 r90 top value=2.2uF
C71 "Capacitor" C0603 37.05,6.55 r0 top value=100nF
C72 "Capacitor" C0402 29.125,32.315 r0 bottom value=100nF
C73 "Capacitor" C0402 32.233,64.033 r0 bottom value=10nF
CN1 "USB_TYPE_C_Receptacle" CON_USB-TYPEC_AMPHENOL_12401826E412A 47.592,73.763 r180 top value=USB_C_12401826E412A
CN2 "Header 4x1" CON_SAMTEC_TSW-104-07-G-S 16.525,80.04 r0 top
CN3 "USB_TYPE_C_Receptacle" CON_USB-TYPEC_AMPHENOL_12401826E412A 22.428,8.736 r0 top value=USB_C_12401826E412A
CN4 "Header 7x2" CON_STDC14_Receiver_MEDIUM_WITH_MIPI10_3D 6.57,64.665 r270 top locked value="Header 5x2"
CN5 "Socket 10x1" CON_SAMTEC_SSQ-110-03-F-S 59.13,38.314 r90 top locked
CN6 "Socket 8x1" CON_SAMTEC_SSQ-108-03-F-S 10.87,31.71 r270 top locked
CN7 "Header 19x2" CON_SAMTEC_TSW-119-09-X-D 4.52,27.9 r270 top locked
CN8 "Socket 6x1" CON_SAMTEC_SSQ-106-03-F-S 10.87,11.39 r270 top locked
CN9 "Socket 8x1" CON_SAMTEC_SSQ-108-03-F-S 59.13,13.93 r90 top locked
CN10 "Header 19x2" CON_SAMTEC_TSW-119-09-X-D 65.48,27.9 r270 top locked
CN11 "Jumper_Header 2x1" CON_SAMTEC_TSW-102-09-X-S 3.25,77.43 r90 top locked value="Header 2x1"
CN12 "Jumper_Header 2x1" CON_SAMTEC_TSW-102-09-X-S 66.75,77.43 r90 top locked value="Header 2x1"
D1 "SCHOTTKY_1A_2K" DIO_SOD523_1A_2K 38.45,7.925 r180 top value=BAT54KFILM
Designator1 "Comment" MIRE_PLACE_SMD_1MM 2.75,72 r0 top
Designator2 "Comment" MIRE_PLACE_SMD_1MM 67.25,65.5 r0 top
Designator3 "Comment" MIRE_PLACE_SMD_1MM 56.15,5.5 r0 top
HW1 "STICKER_PRODUCT" STICKER_PRODUCT_25X9 33.833,51.816 r180 bottom value="Sticker product"
JP1 "Jumper_Header 2x1" CON_SAMTEC_TSW-102-07-G-S 7.9,80.05 r180 top value="Header 2x1"
JP2 "Jumper_Header 2x1" CON_SAMTEC_TSW-102-07-G-S 27.525,80.04 r0 top value="Header 2x1"
JP3 "Jumper_Header 5x2 Fitted 1-2" CON_SAMTEC_TSW-105-07-X-D 57.855,62.945 r90 top value="Header 5x2"
JP4 "Jumper_Header 2x1 Fitted" CON_SAMTEC_TSW-102-07-G-S 32.93,41.225 r180 top value="Header 2x1"
JP5 "Jumper_Header 3x1 Fitted 1-2" CON_SAMTEC_TSW-103-07-F-S 40.375,41.225 r0 top value="Header 3x1"
L1 "Inductor" IND_TDK_VLS252010HBX-1 47.8,64.775 r0 top value=2.2uH
L2 "Inductor" L0805_H0P9 24.725,21.05 r90 top value=2.2uH
LD1 "LED_BICOLOR" LED_BI-GR_WE-150141SV73110 61.72,78.55 r180 top value="Green / Red"
LD2 "LED_green" LED_0603_OSRAM_LG-Q396-PS-35_GREEN_1A2K_H0P4 52.55,55.75 r90 top locked value=GREEN
LD3 "LED_green" LED_0603_OSRAM_LG-Q396-PS-35_GREEN_1A2K_H0P4 60.95,70.35 r0 top locked value=GREEN
LD4 "LED_BICOLOR" LED_BI-GR_WE-150141SV73110 56.675,78.55 r180 top value="Green / Red"
LD6 "LED_green" LED_0603_OSRAM_LG-Q396-PS-35_GREEN_1A2K_H0P4 29.375,2.25 r0 top value=GREEN
Q1 "9013-SOT23" NPN_SOT23 46.875,45.25 r90 top value="NPN SOT23"
Q2 "STL11N3LLH6" MOS_POWERFLAT_3P3X3P3_P065 41.85,8.375 r90 top
R1 "Resistor" R0402 13.075,77.95 r0 top value=47R
R2 "Resistor" R0402 13.075,76.925 r0 top value=47R
R3 "Resistor" R0402 15.5,76.5 r0 top value=100K
R4 "Resistor" R0402 6.45,76.225 r180 top value=100K
R5 "Resistor" R0402 39.247,76 r180 top value=100K
R6 "Resistor" R0402 13.075,75.9 r0 top value=47R
R7 "Resistor" R0402 21.8,75.8 r0 top value=100R
R8 "Resistor" R0402 26.5,75.425 r90 top value=0R
R9 "Resistor" R0402 15.5,75.5 r180 top value=100K
R10 "Resistor" R0402 55.925,75 r270 top value=330R
R11 "Resistor" R0402 57.425,75 r270 top value=1K
R12 "Resistor" R0402 60.97,75 r90 top value=330R
R13 "Resistor" R0402 62.47,75 r270 top value=1K
R14 "Resistor" R0402 30.425,74.925 r90 top value=3K
R15 "Resistor" R0402 6.45,75.15 r180 top value=100K
R16 "Resistor" R0402 39.247,75 r180 top value=5K1
R17 "Resistor" R0402 13.075,74.9 r0 top value=100K
R18 "Resistor" R0402 15.5,74.5 r180 top value=100K
R19 "Resistor" R0402 6.45,74.075 r0 top value=100K
R20 "Resistor" R0402 21.775,74.05 r0 top value=100K
R21 "Resistor" R0402 13.025,73.925 r0 top value=47R
R22 "Resistor" R0402 15.5,73.5 r180 top value=100K
R23 "Resistor" R0402 55,73 r90 top value=1K8
R24 "Resistor" R0402 6.5,73 r0 top value=100K
R25 "Resistor" R0402 21.775,72.975 r0 top value=100K
R26 "Resistor" R0402 13.075,72.95 r180 top value=100K
R27 "Resistor" R0402 35.738,63.983 r90 bottom value=3K
R28 "Resistor" R0402 6.5,72 r0 top value=100K
R29 "Resistor" R0402 63.25,71.75 r180 top value=100K
R30 "Resistor" R0402 53.725,71.3 r180 top value=1K3
R31 "Resistor" R0402 33.761,63.908 r270 bottom value=3K9
R32 "Resistor" R0603 58.25,70.35 r180 top value=510R
R33 "Resistor" R0402 53.725,70.3 r180 top value=3K9
R34 "Resistor" R0402 49.5,70.225 r0 top value=100K
R35 "Resistor" R0402 63.25,69.75 r0 top value=100K
R36 "Resistor" R0402 49.5,69.225 r0 top value=5K1
R37 "Resistor" R0402 50.75,66.75 r0 top value=100K
R38 "Resistor" R0402 38.35,66.25 r90 top value=10K
R39 "Resistor" R0402 39.4,66.25 r90 top value=5K1
R40 "Resistor" R0402 38.725,64.675 r0 top value=0R
R41 "Resistor" R0402 36.225,64.45 r0 top value=10K
R42 "Resistor" R0402 2.325,63.4 r270 top value=100R
R43 "Resistor" R0402 36.225,63.4 r0 top value=10K
R44 "Resistor" R0402 24.8,61.875 r270 top value=10K
R45 "Resistor" R0603 47.525,59.45 r270 top value=0R
R46 "Resistor" R0603 48.95,59.45 r270 top value=0R
R47 "Resistor" R0402 20.5,55.75 r90 top value=0R
R48 "Resistor" R0402 32.775,54.225 r180 top value=100K
R49 "Resistor" R0402 52.55,52.725 r270 top value=270R
R50 "Resistor" R0603 33.1,52.825 r0 top value=0R
R51 "Resistor" R0402 49.675,44.75 r270 top value=100K
R52 "Resistor" R0402 12.3,43.575 r180 top value=1K
R53 "Resistor" R0402 49.675,42.525 r90 top value=47K
R54 "Resistor" R0402 44.125,25.65 r180 top value=10K
R55 "Resistor" R0603 47.075,9.375 r270 top value=49K9
R56 "Resistor" R0603 48.5,9.375 r90 top value=330K
R57 "Resistor" R0402 33.088,5.912 r0 top value=10K
R58 "Resistor" R0402 40.775,5.825 r180 top value=10K
R59 "Resistor" R0402 40.775,4.75 r0 top value=2K4
R60 "Resistor" R0402 34.813,4.113 r90 top value=47K
R61 "Resistor" R0402 29.325,3.475 r0 top value=270R
R62 "Resistor" R0603 47.625,64.325 r0 bottom value=0R
R63 "Resistor" R0603 45,61.25 r0 bottom value=0R
R64 "Resistor" R0603 49.6,59.325 r270 bottom value=19K6
R65 "Resistor" R0402 23.118,63.17 r180 top value=10K
R66 "Resistor" R0402 11.303,64.541 r180 bottom value=0R
R102 "Resistor" R0402 18.5,76.75 r0 bottom value=0R
R103 "Resistor" R0402 18.5,75.75 r0 bottom value=0R
R104 "Resistor" R0402 18.7,74 r0 bottom value=0R
R105 "Resistor" R0402 18.7,73 r0 bottom value=0R
R106 "Resistor" R0402 9.75,76.75 r0 bottom value=0R
R107 "Resistor" R0402 9.75,75.75 r0 bottom value=0R
R108 "Resistor" R0402 9.75,74 r0 bottom value=0R
R109 "Resistor" R0402 10,72.25 r0 bottom value=0R
SB1 "SB_ON" SOLDER-BRIDGE_R0603-0R 40.075,34.55 r270 top
SB2 "SB_ON" SOLDER-BRIDGE_R0603-0R 41.475,34.55 r270 top
SB3 "SB_ON" SOLDER-BRIDGE_R0603-0R 35.975,33.7 r270 top
SB4 "SB_ON" SOLDER-BRIDGE_R0603-0R 37.375,33.7 r270 top
SB5 "SB_ON" SOLDER-BRIDGE_R0603-0R 44.75,62.75 r0 bottom
SB6 "SB_ON" SOLDER-BRIDGE_R0603-0R 47.525,59.8 r0 bottom
SB7 "SB_ON" SOLDER-BRIDGE_R0603-0R 47.525,58.375 r0 bottom
SB8 "SB_ON" SOLDER-BRIDGE_R0603-0R 37.75,45.25 r0 bottom
SB9 "SB_ON" SOLDER-BRIDGE_R0603-0R 15.325,40.625 r270 bottom
SB10 "SB_ON" SOLDER-BRIDGE_R0603-0R 53.425,39.575 r180 bottom
SB11 "SB_ON" SOLDER-BRIDGE_R0603-0R 15.325,37.8 r90 bottom
SB12 "SB_ON" SOLDER-BRIDGE_R0603-0R 30.375,34.575 r270 bottom
SB13 "SB_ON" SOLDER-BRIDGE_R0603-0R 28.275,34.55 r90 bottom
SB14 "SB_ON" SOLDER-BRIDGE_R0603-0R 26.85,34.55 r90 bottom
SB15 "SB_ON" SOLDER-BRIDGE_R0603-0R 22.5,33.95 r180 bottom
SB16 "SB_ON" SOLDER-BRIDGE_R0603-0R 22.5,32.575 r0 bottom
SB17 "SB_ON" SOLDER-BRIDGE_R0603-0R 22.5,31.2 r180 bottom
SB18 "SB_ON" SOLDER-BRIDGE_R0603-0R 37.74,30.425 r270 bottom
SB19 "SB_ON" SOLDER-BRIDGE_R0603-0R 36.39,30.425 r270 bottom
SB20 "SB_ON" SOLDER-BRIDGE_R0603-0R 35.04,30.425 r270 bottom
SB21 "SB_ON" SOLDER-BRIDGE_R0603-0R 30.99,30.425 r270 bottom
SB22 "SB_ON" SOLDER-BRIDGE_R0603-0R 39.15,30.425 r270 bottom
SB23 "SB_ON" SOLDER-BRIDGE_R0603-0R 29.575,30.425 r270 bottom
SB24 "SB_ON" SOLDER-BRIDGE_R0603-0R 28.175,30.425 r270 bottom
SB25 "SB_ON" SOLDER-BRIDGE_R0603-0R 40.56,30.425 r90 bottom
SB26 "SB_ON" SOLDER-BRIDGE_R0603-0R 22.5,29.775 r0 bottom
SB27 "SB_ON" SOLDER-BRIDGE_R0603-0R 23.1,25.725 r270 bottom
SB28 "SB_ON" SOLDER-BRIDGE_R0603-0R 44.275,24.1 r0 bottom
SB29 "SB_ON" SOLDER-BRIDGE_R0603-0R 21.95,21.275 r270 bottom
SB30 "SB_ON" SOLDER-BRIDGE_R0603-0R 20.525,21.275 r270 bottom
SB31 "SB_ON" SOLDER-BRIDGE_R0603-0R 26.225,16.075 r90 bottom
SB32 "SB_ON" SOLDER-BRIDGE_R0603-0R 41.7,15.05 r180 bottom
SB33 "SB_ON" SOLDER-BRIDGE_R0603-0R 41.7,13.625 r180 bottom
SB34 "SB_ON" SOLDER-BRIDGE_R0603-0R 35.75,12.675 r90 bottom
SB35 "SB_ON" SOLDER-BRIDGE_R0603-0R 34.325,12.675 r90 bottom
SB36 "SB_ON" SOLDER-BRIDGE_R0603-0R 32.9,12.675 r90 bottom
SB37 "SB_ON" SOLDER-BRIDGE_R0603-0R 31.475,12.675 r90 bottom
SB38 "SB_ON" SOLDER-BRIDGE_R0603-0R 37.824,12.664 r270 bottom
SB39 "SB_ON" SOLDER-BRIDGE_R0603-0R 39.25,12.65 r270 bottom
SB40 "SB_ON" SOLDER-BRIDGE_R0603-0R 42.025,8 r180 bottom
SB41 "SB_ON" SOLDER-BRIDGE_R0603-0R 44.5,20.85 r180 top
SB42 "SB_ON" SOLDER-BRIDGE_R0603-0R 53.6,43.35 r90 bottom
SB43 "SB_ON" SOLDER-BRIDGE_R0603-0R 53.6,47 r270 bottom
SB44 "SB_ON" SOLDER-BRIDGE_R0603-0R 55.5,43.35 r90 bottom
SB45 "SB_ON" SOLDER-BRIDGE_R0603-0R 55.5,47 r270 bottom
T1 "9013-SOT23" NPN_SOT23 32.588,3.463 r180 top value="NPN SOT23"
TP1 "Test Point" TP_SMD_1MM 26.5,77.6 r90 top
TP2 "Test_Point_PTH_1mm_2mm" TP_PTH_1MM_2MM 43.25,45.25 r0 top value=TP
TP3 "Test_Point_PTH_1mm_2mm" TP_PTH_1MM_2MM 40.25,45.25 r0 top value=TP
U1 "STMPS2151STR" MOS_SOT23-5L 66,70.75 r180 top
U2 "74AVC4TD245BQ" ICC_DHVQFN16-EPAD_SOT763-1_2P5X3P5_H0P85_P050 9.875,74.875 r0 top
U3 "74AVC4TD245BQ" ICC_DHVQFN16-EPAD_SOT763-1_2P5X3P5_H0P85_P050 18.65,74.875 r0 top
U4 "ESD-TRANSIL" ESD_QFN1610_2N_1K_2A 36.75,75.75 r90 top value=ESDA25P35-1U1M
U5 "TPS259535DSG" ICC_WSON8-EPAD_2X2_P050 53.5,68.25 r90 top
U6 "STLINK-V3EC" ICC_UFBGA201_176+25_10X10_P065 29.7,68.4 r90 top value=STM32F723IEK6
U8 "ECMF02-2AMX6" ESD_QFN-6L_1P7X1P5_P050 45.009,70.256 r270 top
U9 "ESDALC6V1W5" ESD_SOT323-5L 14.25,66 r270 top
U10 "ST730M33R" ICC_SOT23-5L_H1P45 42.475,62.375 r0 top
U11 "ESDALC6V1W5" ESD_SOT323-5L 14.25,61.075 r270 top
U12 "ST1PS01EJR" ICC_FLIP-CHIP-BGA8_1P11X1P41_P040 47.825,62.075 r90 top
U13 "ESD-TRANSIL" ESD_ST0201 32.637,55.4 r0 top value=ESDALC6V1-1U2
U14 "ESD-TRANSIL" ESD_ST0201 37.25,51.35 r90 top value=ESDALC6V1-1U2
U15 "LD39050PU33R" ICC_DFN6-EPAD_3X3_P095 32.5,45.45 r270 top
U16 "LD1117S50TR" REG_SOT223-TAB 21.85,43.63 r270 top
U17 "STM32U545RET6Q" ICC_LQFP64_10X10_P050_SOCKET_YAMAICHI_IC149-064-069-B5_NM 35,24.1 r180 top
U18 "USBLC6-2SC6" ESD_SOT23-6L 22.504,14.021 r180 top
U19 "ESD-TRANSIL" ESD_QFN1610_2N_1K_2A 28.55,8.25 r270 top value=ESDA25P35-1U1M
U20 "TCPP01-M12" ICC_QFN12L-EPAD_3X3_P050 37.825,3.875 r0 top
U22 "ADP5301" ICC_WLCSP9_1P65X1P87_P050 47.825,62.075 r270 bottom value=ADP5301ACBZ-2-R7
X1 "XTAL_4_PINS" CRY_NX2016SA_4P 29.675,58.925 r0 top value=24MHz
X2 "XTAL_4_PINS" CRY_NX2016SA_4P 36.656,36.644 r180 top value=16MHz
X3 "XTAL_2_PINS" CRY_NX1610SE_2P 40.79,36.725 r0 top value=32.768kHz

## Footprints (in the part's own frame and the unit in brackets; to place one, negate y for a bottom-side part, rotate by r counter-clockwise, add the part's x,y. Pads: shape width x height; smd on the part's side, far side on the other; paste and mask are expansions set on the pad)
C0402 [mm]
  rect 0.51x0.56 smd mask+0.05: 1(-0.45,0) 2(0.45,0)
  body extent -0.5,-0.3 0.5,0.3, height 0.4
C0603 [mm]
  rect 0.64x0.89 smd mask+0.05: 1(-0.7,0) 2(0.7,0)
  silkscreen extent -0.9,-0.55 1.05,0.55, body extent -0.9,-0.5 0.9,0.5, height 1.4
C0805 [mm]
  rect 0.9x1.4 smd mask+0.05: 1(-0.85,0) 2(0.85,0)
  silkscreen extent -1.3,-0.77 1.3,0.77, body extent -1.1,-0.7 1.1,0.7, height 1.35
CON_SAMTEC_SSQ-106-03-F-S [mm] "MCD-02623"
  rect 1.7x1.7 hole 1 mask+0.05: 1(-6.35,0)
  round 1.7 hole 1 mask+0.05: 2(-3.81,0) 3(-1.27,0) 4(1.27,0) 5(3.81,0) 6(6.35,0)
  silkscreen extent -7.88,-1.21 7.88,1.21, body extent -7.87,-1.21 7.87,1.21, height 8.51
CON_SAMTEC_SSQ-108-03-F-S [mm] "MCD-02624"
  rect 1.7x1.7 hole 1 mask+0.05: 1(-8.89,0)
  round 1.7 hole 1 mask+0.05: 2(-6.35,0) 3(-3.81,0) 4(-1.27,0) 5(1.27,0) 6(3.81,0) 7(6.35,0) 8(8.89,0)
  silkscreen extent -10.41,-1.21 10.41,1.21, body extent -10.41,-1.21 10.41,1.21, height 8.51
CON_SAMTEC_SSQ-110-03-F-S [mm] "MCD-02625"
  rect 1.7x1.7 hole 1 mask+0.05: 1(-11.43,0)
  round 1.7 hole 1 mask+0.05: 2(-8.89,0) 3(-6.35,0) 4(-3.81,0) 5(-1.27,0) 6(1.27,0) 7(3.81,0) 8(6.35,0) 9(8.89,0) 10(11.43,0)
  silkscreen extent -12.95,-1.21 12.95,1.21, body extent -12.95,-1.21 12.95,1.21, height 8.51
CON_SAMTEC_TSW-102-07-G-S [mm]
  rect 1.85x1.85 / inner round 1.85 / far side rect 1.85x1.85 hole 1 mask+0.05: 1(-1.27,0)
  round 1.85 hole 1 mask+0.05: 2(1.27,0)
  silkscreen extent -2.58,-1.3 2.58,1.3, body extent -2.67,-1.3 2.58,1.3, height 8.38
CON_SAMTEC_TSW-102-09-X-S [mm]
  rect 1.85x1.85 / inner round 1.85 / far side rect 1.85x1.85 hole 1 mask+0.05: 1(-1.27,0)
  round 1.85 hole 1 mask+0.05: 2(1.27,0)
  silkscreen extent -2.64,-1.37 2.64,1.37, body extent -2.67,-1.3 2.58,1.3, height 8.38
CON_SAMTEC_TSW-103-07-F-S [mm]
  rect 1.85x1.85 / inner round 1.85 / far side rect 1.85x1.85 hole 1 mask+0.05: 1(-2.54,0)
  round 1.85 hole 1 mask+0.05: 2(0,0) 3(2.54,0)
  silkscreen extent -3.85,-1.3 3.85,1.3, body extent -3.94,-1.37 3.91,1.37, height 8.38
CON_SAMTEC_TSW-104-07-G-S [mm]
  rect 1.85x1.85 / inner round 1.85 / far side rect 1.85x1.85 hole 1 mask+0.05: 1(-3.81,0)
  round 1.85 hole 1 mask+0.05: 2(-1.27,0) 3(1.27,0) 4(3.81,0)
  silkscreen extent -5.12,-1.3 5.12,1.3, body extent -5.21,-1.37 5.18,1.37, height 8.38
CON_SAMTEC_TSW-105-07-X-D [mm]
  rect 1.85x1.85 / inner round 1.85 / far side rect 1.85x1.85 hole 1 mask+0.05: 1(-5.08,-1.27)
  round 1.85 hole 1 mask+0.05: 2(-5.08,1.27) 3(-2.54,-1.27) 4(-2.54,1.27) 5(0,-1.27) 6(0,1.27) 7(2.54,-1.27) 8(2.54,1.27) 9(5.08,-1.27) 10(5.08,1.27)
  silkscreen extent -6.35,-2.54 6.35,2.54, body extent -6.35,-2.54 6.35,2.55, height 8.38
CON_SAMTEC_TSW-119-09-X-D [mm]
  rect 1.85x1.85 / inner round 1.85 / far side rect 1.85x1.85 hole 1 mask+0.05: 1(-22.86,-1.27)
  round 1.85 hole 1 mask+0.05: 2(-22.86,1.27) 3(-20.32,-1.27) 4(-20.32,1.27) 5(-17.78,-1.27) 6(-17.78,1.27) 7(-15.24,-1.27) 8(-15.24,1.27) 9(-12.7,-1.27) 10(-12.7,1.27) 11(-10.16,-1.27) 12(-10.16,1.27) 13(-7.62,-1.27) 14(-7.62,1.27) 15(-5.08,-1.27) 16(-5.08,1.27) 17(-2.54,-1.27) 18(-2.54,1.27) 19(0,-1.27) 20(0,1.27) 21(2.54,-1.27) 22(2.54,1.27) 23(5.08,-1.27) 24(5.08,1.27) 25(7.62,-1.27) 26(7.62,1.27) 27(10.16,-1.27) 28(10.16,1.27) 29(12.7,-1.27) 30(12.7,1.27) 31(15.24,-1.27) 32(15.24,1.27) 33(17.78,-1.27) 34(17.78,1.27) 35(20.32,-1.27) 36(20.32,1.27) 37(22.86,-1.27) 38(22.86,1.27)
  silkscreen extent -24.13,-2.54 24.13,2.54, body extent -24.13,-2.55 24.13,2.54, height 8.38
CON_STDC14_Receiver_MEDIUM_WITH_MIPI10_3D [mm] "compatible with FTSH-105-01-L-DV,-K and FTSH-107-01-L-DV,-K,-A,-P,-ES"
  round 0 hole 1.19 unplated mask+0.05: 0(-5.445,0) 0(5.445,0)
  round 0 hole 0.97 unplated mask+0.038: 0(-3.175,0) 0(3.175,0)
  rect 0.74x2.79 smd mask+0.05: 1(-3.81,-2.032) 2(-3.81,2.032) 3(-2.54,-2.032) 4(-2.54,2.032) 5(-1.27,-2.032) 6(-1.27,2.032) 7(0,-2.032) 8(0,2.032) 9(1.27,-2.032) 10(1.27,2.032) 11(2.54,-2.032) 12(2.54,2.032) 13(3.81,-2.032) 14(3.81,2.032)
  silkscreen extent -6.3,-4.38 6.3,3.6, body extent -6.3,-2.92 6.3,2.92, height 6.6
CON_USB-TYPEC_AMPHENOL_12401826E412A [mm] "MCD-03232"
  round 0 hole 0.65 unplated mask+0.05: 0(-3.6,0)
  round 0 hole 0.65 slot 0.95 at 0 deg unplated mask+0.05: 0(3.6,0)
  rect 0.3x0.7 smd mask+0.05: A1(-2.75,0.66) A2(-2.25,0.66) A3(-1.75,0.66) A4(-1.25,0.66) A5(-0.75,0.66) A6(-0.25,0.66) A7(0.25,0.66) A8(0.75,0.66) A9(1.25,0.66) A10(1.75,0.66) A11(2.25,0.66) A12(2.75,0.66) B1(2.5,-1.04) B2(2,-1.04) B3(1.5,-1.04) B4(1,-1.04) B5(0.5,-1.04) B6(0,-1.04) B7(-0.5,-1.04) B8(-1,-1.04) B9(-1.5,-1.04) B10(-2,-1.04) B11(-2.5,-1.04) B12(-3,-1.04)
  oval 0.8x1.4 hole 0.5 slot 1.1 at 90 deg mask+0.05: SH1(-4.13,-1.25) SH2(4.13,-1.25) SH3(-4.49,-4.7) SH4(4.49,-4.7)
  Top Layer keep-out region: -3.75,-7.24 3.75,-7.24 3.75,-1.95 -3.75,-1.95
  silkscreen extent -4.7,-9.59 4.7,0.91, body extent -4.6,-9.59 4.6,0.91, height 3.25
CRY_NX1610SE_2P [mm] "MCD-02291"
  rect 0.5x1 smd mask+0.05: 1(-0.55,0) 2(0.55,0)
  silkscreen extent -0.13,-0.5 0.13,0.5, body extent -0.8,-0.5 0.8,0.5, height 0.45
CRY_NX2016SA_4P [mm]
  rect 0.85x0.75 smd mask+0.05: 1(-0.675,-0.525) 2(0.675,-0.525) 3(0.675,0.525) 4(-0.675,0.525)
  silkscreen extent -1.22,-1.02 1.05,0.85, body extent -1.05,-0.85 1.05,0.85, height 0.7
DIO_SOD523_1A_2K [mm] "MCD-01677"
  rect 0.65x0.3 smd mask+0.05: 1(-0.675,0) 2(0.675,0)
  silkscreen extent -0.65,-0.45 1.05,0.55, body extent -0.85,-0.45 0.85,0.45, height 0.71
ESD_QFN1610_2N_1K_2A [mm] "DFN, 2-Leads, Body 1.60x1.00mm"
  rect 0.55x0.9 smd mask+0.05: 1(-0.625,0) 2(0.625,0)
  silkscreen extent -1.02,-0.58 0.85,0.58, body extent -0.85,-0.55 0.85,0.55, height 0.6
ESD_QFN-6L_1P7X1P5_P050 [mm]
  rect 0.25x0.6 smd mask+0.05: 1(-0.5,-0.65) 2(0,-0.65) 3(0.5,-0.65) 4(0.5,0.65) 5(0,0.65) 6(-0.5,0.65)
  silkscreen extent -0.9,-0.8 0.9,0.8, body extent -0.9,-0.8 0.9,0.8, height 0.56
ESD_SOT23-6L [mm]
  rect 0.6x1.2 smd mask+0.05: 1(-0.95,-1.15) 2(0,-1.15) 3(0.95,-1.15) 4(0.95,1.15) 5(0,1.15) 6(-0.95,1.15)
  silkscreen extent -1.53,-0.87 1.53,0.87, body extent -1.52,-1.5 1.52,1.5, height 1.45
ESD_SOT323-5L [mm]
  rect 0.4x1.2 smd mask+0.05: 1(-0.65,-0.85) 2(0,-0.85) 3(0.65,-0.85) 4(0.65,0.85) 5(-0.65,0.85)
  silkscreen extent -1.22,-1.21 1.22,0.77, body extent -1.15,-1.05 1.15,1.05, height 1.1
ESD_ST0201 [mm]
  rect 0.425x0.33 smd mask+0.05: 1(-0.312,0) 2(0.312,0)
  silkscreen extent -0.55,-0.3 -0.5,0.3, body extent -0.34,-0.18 0.34,0.18, height 0.34
ICC_DFN6-EPAD_3X3_P095 [mm]
  rect 0.45x0.5 smd mask+0.05: 1(-0.95,-1.3) 2(0,-1.3) 3(0.95,-1.3) 4(0.95,1.3) 5(0,1.3) 6(-0.95,1.3)
  rect 2.5x1.7 smd mask+0.05: EP(0,0)
  silkscreen extent -1.55,-1.55 1.55,1.55, body extent -1.55,-1.55 1.55,1.55, height 1
ICC_DHVQFN16-EPAD_SOT763-1_2P5X3P5_H0P85_P050 [mm] "MCD-01945"
  rect 0.3x0.8 smd mask+0.05: 1(-0.25,1.7) 8(-0.25,-1.7) 9(0.25,-1.7) 16(0.25,1.7)
  rect 0.8x0.3 smd mask+0.05: 2(-1.2,1.25) 3(-1.2,0.75) 4(-1.2,0.25) 5(-1.2,-0.25) 6(-1.2,-0.75) 7(-1.2,-1.25) 10(1.2,-1.25) 11(1.2,-0.75) 12(1.2,-0.25) 13(1.2,0.25) 14(1.2,0.75) 15(1.2,1.25)
  rect 1.2x2.2 smd mask+0.05: 17(0,0)
  silkscreen extent -1.3,-1.8 1.3,1.8, body extent -1.31,-1.81 1.31,1.81, height 1.01
ICC_FLIP-CHIP-BGA8_1P11X1P41_P040 [mm] "MCD-00228"
  round 0.2 smd paste+0.025 mask+0.038: A1(-0.312,0.5) A3(0.312,0.5) B2(0,0.25) C1(-0.312,0) C3(0.312,0) D2(0,-0.25) E1(-0.312,-0.5) E3(0.312,-0.5)
  silkscreen extent -0.7,-0.72 0.57,0.85, body extent -0.57,-0.72 0.57,0.72, height 0.61
ICC_LQFP64_10X10_P050_SOCKET_YAMAICHI_IC149-064-069-B5_NM [mm]
  rect 1x2.5 smd rot 135 mask+0.05: 0(-6,6) 0(6,-6)
  rect 1x2.5 smd rot 45 mask+0.05: 0(-6,-6) 0(6,6)
  round 0.5 hole 1 unplated mask+0.05: 0(0,3.1) 0(0,-3.1)
  rect 0.3x1.7 smd mask+0.05: 1(-3.75,-5.9) 2(-3.25,-5.9) 3(-2.75,-5.9) 4(-2.25,-5.9) 5(-1.75,-5.9) 6(-1.25,-5.9) 7(-0.75,-5.9) 8(-0.25,-5.9) 9(0.25,-5.9) 10(0.75,-5.9) 11(1.25,-5.9) 12(1.75,-5.9) 13(2.25,-5.9) 14(2.75,-5.9) 15(3.25,-5.9) 16(3.75,-5.9) 33(3.75,5.9) 34(3.25,5.9) 35(2.75,5.9) 36(2.25,5.9) 37(1.75,5.9) 38(1.25,5.9) 39(0.75,5.9) 40(0.25,5.9) 41(-0.25,5.9) 42(-0.75,5.9) 43(-1.25,5.9) 44(-1.75,5.9) 45(-2.25,5.9) 46(-2.75,5.9) 47(-3.25,5.9) 48(-3.75,5.9)
  rect 1.7x0.3 smd mask+0.05: 17(5.9,-3.75) 18(5.9,-3.25) 19(5.9,-2.75) 20(5.9,-2.25) 21(5.9,-1.75) 22(5.9,-1.25) 23(5.9,-0.75) 24(5.9,-0.25) 25(5.9,0.25) 26(5.9,0.75) 27(5.9,1.25) 28(5.9,1.75) 29(5.9,2.25) 30(5.9,2.75) 31(5.9,3.25) 32(5.9,3.75) 49(-5.9,3.75) 50(-5.9,3.25) 51(-5.9,2.75) 52(-5.9,2.25) 53(-5.9,1.75) 54(-5.9,1.25) 55(-5.9,0.75) 56(-5.9,0.25) 57(-5.9,-0.25) 58(-5.9,-0.75) 59(-5.9,-1.25) 60(-5.9,-1.75) 61(-5.9,-2.25) 62(-5.9,-2.75) 63(-5.9,-3.25) 64(-5.9,-3.75)
  silkscreen extent -5.05,-5.05 5.05,5.05, body extent -6,-6 6,6, height 1.6
ICC_QFN12L-EPAD_3X3_P050 [mm] "MCD-01809"
  rect 0.3x0.75 smd mask+0.05: 1(-0.5,-1.425) 2(0,-1.425) 3(0.5,-1.425) 7(0.5,1.425) 8(0,1.425) 9(-0.5,1.425)
  rect 0.75x0.3 smd mask+0.05: 4(1.425,-0.5) 5(1.425,0) 6(1.425,0.5) 10(-1.425,0.5) 11(-1.425,0) 12(-1.425,-0.5)
  rect 1.7x1.7 smd mask+0.05: 13(0,0)
  body extent -1.55,-1.55 1.55,1.55, height 0.8
ICC_SOT23-5L_H1P45 [mm]
  rect 0.6x1.3 smd mask+0.05: 1(-0.95,-1.1) 2(0,-1.1) 3(0.95,-1.1) 4(0.95,1.1) 5(-0.95,1.1)
  silkscreen extent -1.75,-1.68 1.6,0.97, body extent -1.52,-1.25 1.52,1.25, height 1.45
ICC_UFBGA201_176+25_10X10_P065 [mm] "IPC"
  round 0.25 smd mask+0.038: A1(-4.55,4.55) A2(-3.9,4.55) A3(-3.25,4.55) A4(-2.6,4.55) A5(-1.95,4.55) A6(-1.3,4.55) A7(-0.65,4.55) A8(0,4.55) A9(0.65,4.55) A10(1.3,4.55) A11(1.95,4.55) A12(2.6,4.55) A13(3.25,4.55) A14(3.9,4.55) A15(4.55,4.55) B1(-4.55,3.9) B2(-3.9,3.9) B3(-3.25,3.9) B4(-2.6,3.9) B5(-1.95,3.9) B6(-1.3,3.9) B7(-0.65,3.9) B8(0,3.9) B9(0.65,3.9) B10(1.3,3.9) B11(1.95,3.9) B12(2.6,3.9) B13(3.25,3.9) B14(3.9,3.9) B15(4.55,3.9) C1(-4.55,3.25) C2(-3.9,3.25) C3(-3.25,3.25) C4(-2.6,3.25) C5(-1.95,3.25) C6(-1.3,3.25) C7(-0.65,3.25) C8(0,3.25) C9(0.65,3.25) C10(1.3,3.25) C11(1.95,3.25) C12(2.6,3.25) C13(3.25,3.25) C14(3.9,3.25) C15(4.55,3.25) D1(-4.55,2.6) D2(-3.9,2.6) D3(-3.25,2.6) D4(-2.6,2.6) D5(-1.95,2.6) D6(-1.3,2.6) D7(-0.65,2.6) D8(0,2.6) D9(0.65,2.6) D10(1.3,2.6) D11(1.95,2.6) D12(2.6,2.6) D13(3.25,2.6) D14(3.9,2.6) D15(4.55,2.6) E1(-4.55,1.95) E2(-3.9,1.95) E3(-3.25,1.95) E4(-2.6,1.95) E12(2.6,1.95) E13(3.25,1.95) E14(3.9,1.95) E15(4.55,1.95) F1(-4.55,1.3) F2(-3.9,1.3) F3(-3.25,1.3) F4(-2.6,1.3) F6(-1.3,1.3) F7(-0.65,1.3) F8(0,1.3) F9(0.65,1.3) F10(1.3,1.3) F12(2.6,1.3) F13(3.25,1.3) F14(3.9,1.3) F15(4.55,1.3) G1(-4.55,0.65) G2(-3.9,0.65) G3(-3.25,0.65) G4(-2.6,0.65) G6(-1.3,0.65) G7(-0.65,0.65) G8(0,0.65) G9(0.65,0.65) G10(1.3,0.65) G12(2.6,0.65) G13(3.25,0.65) G14(3.9,0.65) G15(4.55,0.65) H1(-4.55,0) H2(-3.9,0) H3(-3.25,0) H4(-2.6,0) H6(-1.3,0) H7(-0.65,0) H8(0,0) H9(0.65,0) H10(1.3,0) H12(2.6,0) H13(3.25,0) H14(3.9,0) H15(4.55,0) J1(-4.55,-0.65) J2(-3.9,-0.65) J3(-3.25,-0.65) J4(-2.6,-0.65) J6(-1.3,-0.65) J7(-0.65,-0.65) J8(0,-0.65) J9(0.65,-0.65) J10(1.3,-0.65) J12(2.6,-0.65) J13(3.25,-0.65) J14(3.9,-0.65) J15(4.55,-0.65) K1(-4.55,-1.3) K2(-3.9,-1.3) K3(-3.25,-1.3) K4(-2.6,-1.3) K6(-1.3,-1.3) K7(-0.65,-1.3) K8(0,-1.3) K9(0.65,-1.3) K10(1.3,-1.3) K12(2.6,-1.3) K13(3.25,-1.3) K14(3.9,-1.3) K15(4.55,-1.3) L1(-4.55,-1.95) L2(-3.9,-1.95) L3(-3.25,-1.95) L4(-2.6,-1.95) L12(2.6,-1.95) L13(3.25,-1.95) L14(3.9,-1.95) L15(4.55,-1.95) M1(-4.55,-2.6) M2(-3.9,-2.6) M3(-3.25,-2.6) M4(-2.6,-2.6) M5(-1.95,-2.6) M6(-1.3,-2.6) M7(-0.65,-2.6) M8(0,-2.6) M9(0.65,-2.6) M10(1.3,-2.6) M11(1.95,-2.6) M12(2.6,-2.6) M13(3.25,-2.6) M14(3.9,-2.6) M15(4.55,-2.6) N1(-4.55,-3.25) N2(-3.9,-3.25) N3(-3.25,-3.25) N4(-2.6,-3.25) N5(-1.95,-3.25) N6(-1.3,-3.25) N7(-0.65,-3.25) N8(0,-3.25) N9(0.65,-3.25) N10(1.3,-3.25) N11(1.95,-3.25) N12(2.6,-3.25) N13(3.25,-3.25) N14(3.9,-3.25) N15(4.55,-3.25) P1(-4.55,-3.9) P2(-3.9,-3.9) P3(-3.25,-3.9) P4(-2.6,-3.9) P5(-1.95,-3.9) P6(-1.3,-3.9) P7(-0.65,-3.9) P8(0,-3.9) P9(0.65,-3.9) P10(1.3,-3.9) P11(1.95,-3.9) P12(2.6,-3.9) P13(3.25,-3.9) P14(3.9,-3.9) P15(4.55,-3.9) R1(-4.55,-4.55) R2(-3.9,-4.55) R3(-3.25,-4.55) R4(-2.6,-4.55) R5(-1.95,-4.55) R6(-1.3,-4.55) R7(-0.65,-4.55) R8(0,-4.55) R9(0.65,-4.55) R10(1.3,-4.55) R11(1.95,-4.55) R12(2.6,-4.55) R13(3.25,-4.55) R14(3.9,-4.55) R15(4.55,-4.55)
  silkscreen extent -5.22,-5.07 5.07,5.23, body extent -5.07,-5.07 5.07,5.07, height 0.61
ICC_WLCSP9_1P65X1P87_P050 [mm]
  round 0.3 smd mask+0.025: A1(-0.5,0.5) A2(0,0.5) A3(0.5,0.5) B1(-0.5,0) B2(0,0) B3(0.5,0) C1(-0.5,-0.5) C2(0,-0.5) C3(0.5,-0.5)
  silkscreen extent -0.97,-0.97 0.85,1.1, body extent -0.85,-0.97 0.85,0.97, height 0.67
ICC_WSON8-EPAD_2X2_P050 [mm] "MCD-02194"
  rect 0.5x0.3 smd paste+0 mask+0.05: 1(-0.9,0.75) 2(-0.9,0.25) 3(-0.9,-0.25) 4(-0.9,-0.75) 5(0.9,-0.75) 6(0.9,-0.25) 7(0.9,0.25) 8(0.9,0.75)
  rect 0.9x1.6 smd paste+0 mask+0.05: 9(0,0)
  silkscreen extent -0.5,-1 0.5,1, body extent -1,-1 1,1, height 0.81
IND_TDK_VLS252010HBX-1 [mm]
  rect 0.6x2 smd mask+0.05: 1(-0.95,0) 2(0.95,0)
  silkscreen extent -1.38,-1.12 1.38,1.12, body extent -1.35,-1.1 1.35,1.1, height 1.01
L0805_H0P9 [mm]
  rect 1.1x1.6 smd mask+0.05: 1(-0.75,0) 2(0.75,0)
  silkscreen extent -0.08,-0.7 0.08,0.7, body extent -1.07,-0.7 1.07,0.7, height 1.2
LED_0603_OSRAM_LG-Q396-PS-35_GREEN_1A2K_H0P4 [mm]
  rect 0.8x0.8 smd mask+0.05: 1(-0.75,0) 2(0.75,0)
  silkscreen extent -0.85,-0.53 1.28,0.53, body extent -0.85,-0.45 0.85,0.45, height 0.6
LED_BI-GR_WE-150141SV73110 [mm] "MCD-02631"
  rect 1.1x1.5 smd mask+0.05: 1(-0.75,1.5) 2(0.75,1.5) 3(-0.75,-1.5) 4(0.75,-1.5)
  silkscreen extent -1.65,-1.85 1.5,1.7, body extent -1.5,-1.85 1.5,1.85, height 2.1
MIRE_PLACE_SMD_1MM [mm]
  round 1 smd paste-10 mask+1: 1(0,0)
  Top Layer keep-out circle w0.01: c0,0 r1.5
MOS_POWERFLAT_3P3X3P3_P065 [mm] "MCD-01126"
  rect 0.4x0.75 smd mask+0.05: 1(-0.975,-1.525) 2(-0.325,-1.525) 3(0.325,-1.525) 4(0.975,-1.525) 6(0.325,1.525) 7(-0.325,1.525)
  rect 0.45x0.75 smd mask+0.05: 5(1,1.525) 8(-1,1.525)
  Top Layer region: -1.755,0.2 -1.755,-0.2 -1.225,-0.2 -1.225,-0.5 1.225,-0.5 1.225,-0.2 1.755,-0.2 1.755,0.2 1.225,0.2 1.225,1.9 -1.225,1.9 -1.225,0.2
  silkscreen extent -1.63,-1.55 1.63,1.55, body extent -1.75,-1.75 1.75,1.75, height 0.91
MOS_SOT23-5L [mm]
  rect 0.6x1.3 smd mask+0.05: 1(-0.95,-1.1) 2(0,-1.1) 3(0.95,-1.1) 4(0.95,1.1) 5(-0.95,1.1)
  silkscreen extent -1.6,-0.95 1.6,0.97, body extent -1.52,-1.25 1.52,1.25, height 1.45
NPN_SOT23 [mm]
  rect 1x1.4 smd mask+0.05: 1(-0.95,-1.1) 2(0.95,-1.1) 3(0,1.1)
  silkscreen extent -1.63,-0.82 1.63,0.82, body extent -1.56,-1.25 1.56,1.25, height 1.1
R0402 [mm]
  rect 0.51x0.7 smd mask+0.05: 1(-0.45,0) 2(0.45,0)
  body extent -0.52,-0.3 0.52,0.3, height 0.4
R0603 [mm]
  rect 0.64x1 smd mask+0.05: 1(-0.7,0) 2(0.7,0)
  silkscreen extent -1.05,-0.58 1.05,0.58, body extent -0.9,-0.5 0.9,0.5, height 0.56
REG_SOT223-TAB [mm]
  rect 1.5x1.65 smd mask+0.05: 1(-2.3,-3.175) 2(0,-3.175) 3(2.3,-3.175)
  rect 3.5x1.65 smd mask+0.05: 4(0,3.175)
  silkscreen extent -3.35,-2.15 3.35,2.12, body extent -3.35,-3.48 3.35,3.48, height 1.8
SOLDER-BRIDGE_R0603-0R [mil]
  round 10 smd paste-393.7: 1(-19.68,0) 2(23.62,0)
  Top Layer region: -3.94,19.69 15.75,0 -3.94,-19.69 47.24,-19.69 47.24,19.68
  Top Layer region: -47.24,-19.69 -47.24,19.68 -17.72,19.69 1.97,0 -17.72,-19.69
  silkscreen extent -50,-23 50,23, body extent -36,-20 36,20, height 22
STICKER_PRODUCT_25X9 [mm] "Sticker to mention board CPN code"
  silkscreen extent -12.5,-4.5 12.5,4.5
SWI_APEM_ADTSM644KV_BLACK [mm] "MCD-02524"
  rect 1.55x1.3 smd mask+0.05: 1(-3.975,-2.25) 2(3.975,-2.25) 3(-3.975,2.25) 4(3.975,2.25)
  silkscreen extent -3.1,-3.1 3.1,3.1, body extent -4.5,-3.1 4.5,3.1, height 7.3
SWI_APEM_ADTSM644SV_BLUE [mm] "MCD-02524"
  rect 1.55x1.3 smd mask+0.05: 1(-3.975,-2.25) 2(3.975,-2.25) 3(-3.975,2.25) 4(3.975,2.25)
  silkscreen extent -3.1,-3.1 3.1,3.1, body extent -4.5,-3.1 4.5,3.1, height 7.3
TP_PTH_1MM_2MM [mm] "MCD-01506"
  round 2 hole 1 mask+0.05: 1(0,0)
  silkscreen extent -1.2,-1.2 1.2,1.2
TP_SMD_1MM [mm]
  round 1 smd paste-10 mask+0.05: 1(0,0)
  silkscreen extent -0.7,-0.7 0.7,0.7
